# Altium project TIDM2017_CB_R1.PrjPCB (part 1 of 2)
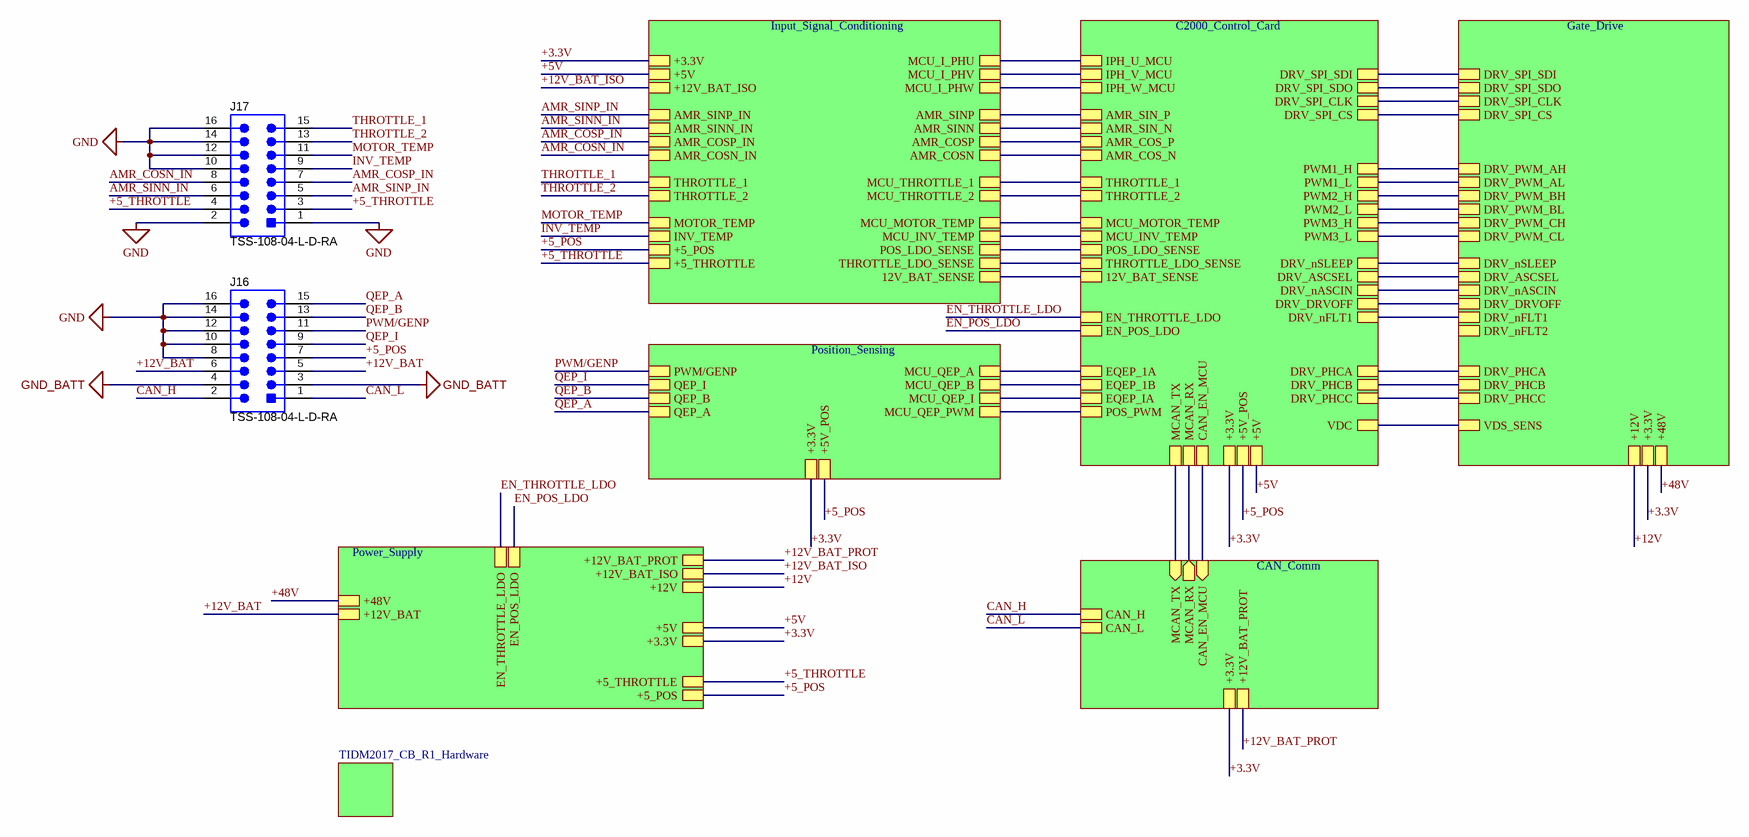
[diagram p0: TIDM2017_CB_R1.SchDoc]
CopyrightYear: 2023; PCB_Layout: Bhanu Vankayalapati; PCB_Rev: C1; PRJ_Customer: Public Release; PRJ_Engineer: Bhanu Vankayalapati; PRJ_Number: TIDM-2017; PRJ_Title: Control_Board_2W_Traction_Inverter; SCH_Rev: C1; TechSupport: http://www.ti.com/support; TID: N/A
8 sheets, 247 parts. Net scope: hierarchical (ports join the sheet entries above them; power ports are global).
Board file: TIDM2017_CB_R1.PcbDoc
Sheets:
  TIDM2017_CB_R1.SchDoc
     = C2000_Control_Card.SchDoc
    Designator = CAN_Comm.SchDoc
    Designator = Input_Signal_Conditioning.SchDoc
    Designator = Gate_Drive.SchDoc
    Designator = Power_Supply.SchDoc
    Designator = Position_Sensing.SchDoc
    Designator = TIDM2017_CB_R1_Hardware.SchDoc

## Sheet TIDM2017_CB_R1.SchDoc
size 431 x 279 mm; Date: Not shown in title block; ApprovedBy: Not shown in title block; CheckedBy: Not shown in title block; Author: Not shown in title block; CompanyName: Not shown in title block; DrawnBy: Bhanu Vankayalapati; Engineer: Not shown in title block; Organization: Not shown in title block; Address1: Not shown in title block; Address2: Not shown in title block; Address3: Not shown in title block; Address4: Not shown in title block; DocumentNumber: 2; Revision: Use project parameter SCH_Rev; SheetNumber: 1; SheetTotal: 2; PageSetup: Record=PageOptions¦CenterHorizontal=True¦CenterVertical=True¦PrintScale=1.00¦XCorrection=1.00¦YCorrection=1.00¦PrintKind=0¦BorderSize=5000000¦LeftOffset=0¦BottomOffset=0¦Orientation=2¦PaperLength=1000¦PaperWidth=1000¦Scale=100¦PaperSource=15¦PrintQuality=600¦MediaType=1¦DitherType=10¦PaperKind=Letter¦PrintScaleMode=1

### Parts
J16  TSS-108-04-L-D-RA  [Samtec_TSS-108-04-x-D-RA]
J17  TSS-108-04-L-D-RA  [Samtec_TSS-108-04-x-D-RA]

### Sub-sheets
Designator = CAN_Comm: MCAN_TX (in), MCAN_RX (out), CAN_H, CAN_L, CAN_EN_MCU (in), +3.3V, +12V_BAT_PROT
Designator = Input_Signal_Conditioning: MCU_I_PHU, MCU_I_PHV, MCU_I_PHW, +3.3V, MCU_THROTTLE_1, MCU_THROTTLE_2, THROTTLE_1, THROTTLE_2, MCU_MOTOR_TEMP, MOTOR_TEMP, AMR_SINP_IN, AMR_SINP, AMR_SINN_IN, AMR_SINN, AMR_COSP_IN, AMR_COSP, AMR_COSN_IN, AMR_COSN, MCU_INV_TEMP, INV_TEMP, +5_POS, POS_LDO_SENSE, +5_THROTTLE, THROTTLE_LDO_SENSE, +5V, +12V_BAT_ISO, 12V_BAT_SENSE
Designator = Gate_Drive: DRV_SPI_SDI, DRV_SPI_SDO, DRV_SPI_CLK, DRV_SPI_CS, DRV_PWM_AH, DRV_PWM_AL, DRV_PWM_BH, DRV_PWM_BL, DRV_PWM_CH, DRV_PWM_CL, DRV_nSLEEP, DRV_ASCSEL, DRV_nASCIN, DRV_DRVOFF, +12V, DRV_PHCA, DRV_PHCB, DRV_PHCC, DRV_nFLT1, DRV_nFLT2, +3.3V, +48V, VDS_SENS
Designator = Power_Supply: +12V, +48V, +12V_BAT_ISO, +5V, EN_THROTTLE_LDO, EN_POS_LDO, +3.3V, +12V_BAT_PROT, +12V_BAT, +5_POS, +5_THROTTLE
Designator = Position_Sensing: MCU_QEP_A, MCU_QEP_B, MCU_QEP_I, PWM/GENP, MCU_QEP_PWM, QEP_A, QEP_B, QEP_I, +3.3V, +5V_POS
Designator = TIDM2017_CB_R1_Hardware: no entries
? = C2000_Control_Card: DRV_SPI_SDI, DRV_SPI_SDO, DRV_SPI_CLK, DRV_SPI_CS, PWM2_H, PWM2_L, PWM1_H, PWM1_L, PWM3_H, PWM3_L, DRV_PHCC, DRV_PHCB, DRV_PHCA, EQEP_IA, EQEP_1A, EQEP_1B, POS_PWM, MCAN_TX, MCAN_RX, CAN_EN_MCU, +3.3V, +5V, +5V_POS, DRV_nFLT1, DRV_DRVOFF, DRV_ASCSEL, DRV_nASCIN, DRV_nSLEEP, IPH_V_MCU, IPH_U_MCU, AMR_COS_P, AMR_SIN_P, THROTTLE_1, AMR_COS_N, AMR_SIN_N, THROTTLE_2, IPH_W_MCU, VDC, THROTTLE_LDO_SENSE, POS_LDO_SENSE, MCU_INV_TEMP, MCU_MOTOR_TEMP, 12V_BAT_SENSE, EN_THROTTLE_LDO, EN_POS_LDO

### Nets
+3.3V: sheet /+3.3V, sheet Designator/+3.3V, sheet Designator/+3.3V, sheet Designator/+3.3V, sheet Designator/+3.3V, sheet Designator/+3.3V
+5V: sheet /+5V, sheet Designator/+5V, sheet Designator/+5V
GND: J16.8 J16.10 J16.12 J16.14 J16.16 J17.1 J17.2 J17.10 J17.12 J17.14 J17.16
GND_BATT: J16.3 J16.4
12V_BAT_SENSE: sheet /12V_BAT_SENSE, sheet Designator/12V_BAT_SENSE
+5_POS: J16.7 ; sheet /+5V_POS, sheet Designator/+5_POS, sheet Designator/+5_POS, sheet Designator/+5V_POS
+5_THROTTLE: J17.3 J17.4 ; sheet Designator/+5_THROTTLE, sheet Designator/+5_THROTTLE
+12V: sheet Designator/+12V, sheet Designator/+12V
+12V_BAT: J16.5 J16.6 ; sheet Designator/+12V_BAT
+12V_BAT_ISO: sheet Designator/+12V_BAT_ISO, sheet Designator/+12V_BAT_ISO  [project net +12_Bat_Iso]
+12V_BAT_PROT: sheet Designator/+12V_BAT_PROT, sheet Designator/+12V_BAT_PROT
+48V: sheet Designator/+48V, sheet Designator/+48V
AMR_COS_N: sheet /AMR_COS_N, sheet Designator/AMR_COSN
AMR_COS_P: sheet /AMR_COS_P, sheet Designator/AMR_COSP
AMR_COSN_IN: J17.8 ; sheet Designator/AMR_COSN_IN
AMR_COSP_IN: J17.7 ; sheet Designator/AMR_COSP_IN
AMR_SIN_N: sheet /AMR_SIN_N, sheet Designator/AMR_SINN
AMR_SIN_P: sheet /AMR_SIN_P, sheet Designator/AMR_SINP
AMR_SINN_IN: J17.6 ; sheet Designator/AMR_SINN_IN
AMR_SINP_IN: J17.5 ; sheet Designator/AMR_SINP_IN
CAN_EN_MCU: sheet /CAN_EN_MCU, sheet Designator/CAN_EN_MCU
CAN_H: J16.2 ; sheet Designator/CAN_H
CAN_L: J16.1 ; sheet Designator/CAN_L
DRV_ASCSEL: sheet /DRV_ASCSEL, sheet Designator/DRV_ASCSEL
DRV_DRVOFF: sheet /DRV_DRVOFF, sheet Designator/DRV_DRVOFF
DRV_nASCIN: sheet /DRV_nASCIN, sheet Designator/DRV_nASCIN
DRV_nFLT1: sheet /DRV_nFLT1, sheet Designator/DRV_nFLT1
DRV_nSLEEP: sheet /DRV_nSLEEP, sheet Designator/DRV_nSLEEP
DRV_PHCA: sheet /DRV_PHCA, sheet Designator/DRV_PHCA
DRV_PHCB: sheet /DRV_PHCB, sheet Designator/DRV_PHCB
DRV_PHCC: sheet /DRV_PHCC, sheet Designator/DRV_PHCC
DRV_PWM_AH: sheet /PWM1_H, sheet Designator/DRV_PWM_AH
DRV_PWM_AL: sheet /PWM1_L, sheet Designator/DRV_PWM_AL
DRV_PWM_BH: sheet /PWM2_H, sheet Designator/DRV_PWM_BH
DRV_PWM_BL: sheet /PWM2_L, sheet Designator/DRV_PWM_BL
DRV_PWM_CH: sheet /PWM3_H, sheet Designator/DRV_PWM_CH
DRV_PWM_CL: sheet /PWM3_L, sheet Designator/DRV_PWM_CL
DRV_SPI_CLK: sheet /DRV_SPI_CLK, sheet Designator/DRV_SPI_CLK
DRV_SPI_CS: sheet /DRV_SPI_CS, sheet Designator/DRV_SPI_CS
DRV_SPI_SDI: sheet /DRV_SPI_SDI, sheet Designator/DRV_SPI_SDI
DRV_SPI_SDO: sheet /DRV_SPI_SDO, sheet Designator/DRV_SPI_SDO
EN_POS_LDO: sheet /EN_POS_LDO, sheet Designator/EN_POS_LDO
EN_THROTTLE_LDO: sheet /EN_THROTTLE_LDO, sheet Designator/EN_THROTTLE_LDO
ILEM_A_MCU: sheet /IPH_U_MCU, sheet Designator/MCU_I_PHU
ILEM_B_MCU: sheet /IPH_V_MCU, sheet Designator/MCU_I_PHV
ILEM_C_MCU: sheet /IPH_W_MCU, sheet Designator/MCU_I_PHW
INV_TEMP: J17.9 ; sheet Designator/INV_TEMP
MCAN_RX: sheet /MCAN_RX, sheet Designator/MCAN_RX
MCAN_TX: sheet /MCAN_TX, sheet Designator/MCAN_TX
MCU_INV_TEMP: sheet /MCU_INV_TEMP, sheet Designator/MCU_INV_TEMP
MCU_MOTOR_TEMP: sheet /MCU_MOTOR_TEMP, sheet Designator/MCU_MOTOR_TEMP
MCU_QEP_A: sheet /EQEP_1A, sheet Designator/MCU_QEP_A
MCU_QEP_B: sheet /EQEP_1B, sheet Designator/MCU_QEP_B
MCU_QEP_I: sheet /EQEP_IA, sheet Designator/MCU_QEP_I
MCU_QEP_PWM: sheet /POS_PWM, sheet Designator/MCU_QEP_PWM
MCU_THROTTLE_1: sheet /THROTTLE_1, sheet Designator/MCU_THROTTLE_1
MCU_THROTTLE_2: sheet /THROTTLE_2, sheet Designator/MCU_THROTTLE_2
MOTOR_TEMP: J17.11 ; sheet Designator/MOTOR_TEMP
POS_LDO_SENSE: sheet /POS_LDO_SENSE, sheet Designator/POS_LDO_SENSE
PWM/GENP: J16.11 ; sheet Designator/PWM/GENP  [project net EQEP_PWM]
QEP_A: J16.15 ; sheet Designator/QEP_A  [project net EQEP_A]
QEP_B: J16.13 ; sheet Designator/QEP_B  [project net EQEP_B]
QEP_I: J16.9 ; sheet Designator/QEP_I  [project net EQEP_I]
THROTTLE_1: J17.15 ; sheet Designator/THROTTLE_1
THROTTLE_2: J17.13 ; sheet Designator/THROTTLE_2
THROTTLE_LDO_SENSE: sheet /THROTTLE_LDO_SENSE, sheet Designator/THROTTLE_LDO_SENSE
VDC: sheet /VDC, sheet Designator/VDS_SENS

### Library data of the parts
J16 J17 = CMP-0075673-1: Header (Shrouded), 2.54mm, 8x2, Tin, R/A, TH; Manufacturer: Samtec; Pitch_mm: 2.54; Gender: Male; Cert_UL: Y; CT: False; Row_Count: 2

## Sheet C2000_Control_Card.SchDoc
size 431 x 279 mm; Date: Not shown in title block; ApprovedBy: Not shown in title block; CheckedBy: Not shown in title block; Author: Not shown in title block; CompanyName: Not shown in title block; Engineer: Not shown in title block; Organization: Not shown in title block; Address1: Not shown in title block; Address2: Not shown in title block; Address3: Not shown in title block; Address4: Not shown in title block; DocumentNumber: 2; Revision: Use project parameter SCH_Rev; SheetNumber: 2; SheetTotal: 3; PageSetup: Record=PageOptions¦CenterHorizontal=True¦CenterVertical=True¦PrintScale=1.00¦XCorrection=1.00¦YCorrection=1.00¦PrintKind=0¦BorderSize=5000000¦LeftOffset=0¦BottomOffset=0¦Orientation=2¦PaperLength=1000¦PaperWidth=1000¦Scale=100¦PaperSource=15¦PrintQuality=600¦MediaType=1¦DitherType=10¦PaperKind=Letter¦PrintScaleMode=1
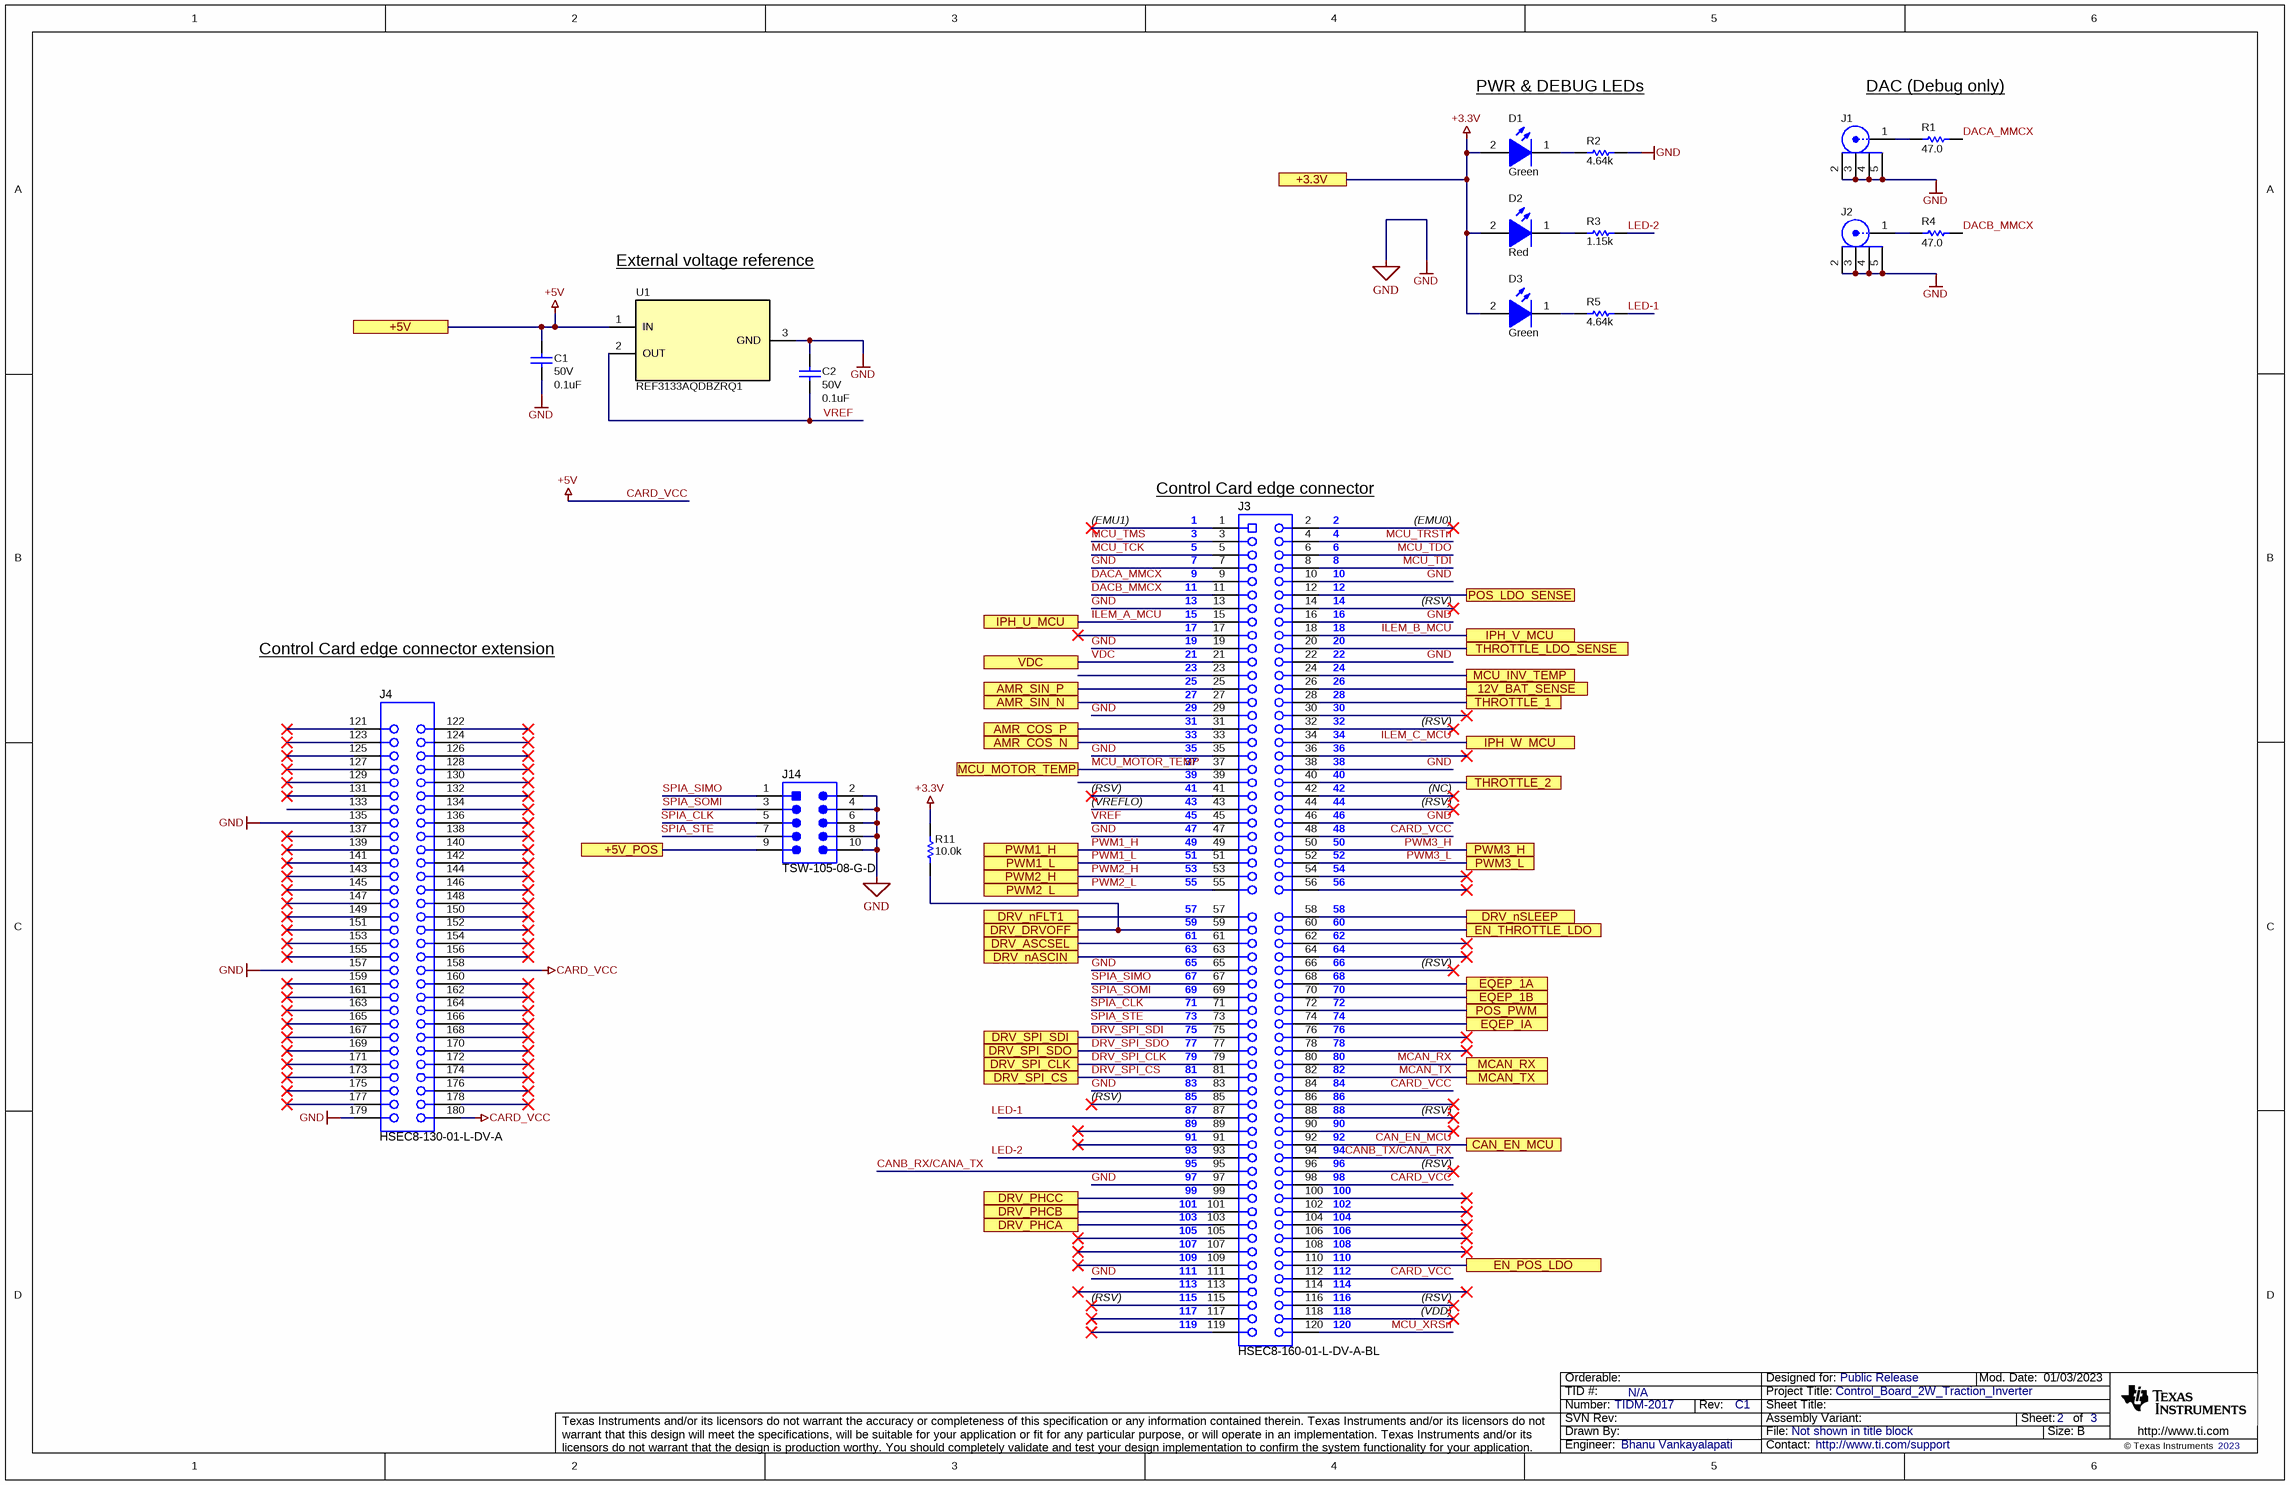
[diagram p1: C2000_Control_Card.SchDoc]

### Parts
C1  VDC_V: 50V  ValueDisplayed: 0.1uF  [0603]  (hidden comment: CGA3E2X7R1H104K080AA)
C2  VDC_V: 50V  ValueDisplayed: 0.1uF  [0603]  (hidden comment: CGA3E2X7R1H104K080AA)
D1  value Green  [WL-SMCW_GREEN]  (hidden comment: 150060GS75000)
D2  value Red  [WL-SMCW_RED]  (hidden comment: 150060RS75000)
D3  value Green  [WL-SMCW_GREEN]  (hidden comment: 150060GS75000)
J1  0734151471  [Molex_0734151471]  (value not drawn)
J2  0734151471  [Molex_0734151471]  (value not drawn)
J3  HSEC8-160-01-L-DV-A-BL  [controlCARD-120HSEC]
J4  HSEC8-130-01-L-DV-A  [controlCARD-180HSEC-60pinAddon]
J14  TSW-105-08-G-D  [Samtec_TSW-105-08-x-D]
R1  ValueDisplayed: 47.0  [0603]  (hidden comment: CRCW060347R0FKEA)
R2  ValueDisplayed: 4.64k  [0603]  (hidden comment: CRCW06034K64FKEA)
R3  ValueDisplayed: 1.15k  [0603]  (hidden comment: CRCW06031K15FKEA)
R4  ValueDisplayed: 47.0  [0603]  (hidden comment: CRCW060347R0FKEA)
R5  ValueDisplayed: 4.64k  [0603]  (hidden comment: CRCW06034K64FKEA)
R11  ValueDisplayed: 10.0k  [0603]  (hidden comment: CRCW060310K0FKEA)
U1  REF3133AQDBZRQ1  [DBZ0003A_N]

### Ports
12V_BAT_SENSE, +3.3V, +5V, +5V_POS, AMR_COS_N, AMR_COS_P, AMR_SIN_N, AMR_SIN_P, CAN_EN_MCU, DRV_ASCSEL, DRV_DRVOFF, DRV_nASCIN, DRV_nFLT1, DRV_nSLEEP, DRV_PHCA, DRV_PHCB, DRV_PHCC, DRV_SPI_CLK, DRV_SPI_CS, DRV_SPI_SDI, DRV_SPI_SDO, EN_POS_LDO, EN_THROTTLE_LDO, EQEP_1A, EQEP_1B, EQEP_IA, IPH_U_MCU, IPH_V_MCU, IPH_W_MCU, MCAN_RX, MCAN_TX, MCU_INV_TEMP, MCU_MOTOR_TEMP, POS_LDO_SENSE, POS_PWM, PWM1_H, PWM1_L, PWM2_H, PWM2_L, PWM3_H, PWM3_L, THROTTLE_1, THROTTLE_2, THROTTLE_LDO_SENSE, VDC

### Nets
+3.3V: D1.2(A) D2.2(A) D3.2(A) R11.2 ; port +3.3V
+5V: C1.1 J3.48 J3.84 J3.98 J3.112 J4.158 J4.180 U1.1(IN) ; port +5V  [also labelled CARD_VCC]
GND: C1.2 C2.1 J1.2 J1.3 J1.4 J1.5 J2.2 J2.3 J2.4 J2.5 J3.7 J3.10 J3.13 J3.16 J3.19 J3.22 J3.29 J3.35 J3.38 J3.46 J3.47 J3.65 J3.83 J3.97 J3.111 J4.135 J4.157 J4.179 J14.2 J14.4 J14.6 J14.8 J14.10 R2.1 U1.3(GND)
12V_BAT_SENSE: J3.26 ; port 12V_BAT_SENSE
+5_POS: J14.9 ; port +5V_POS
AMR_COS_N: J3.33 ; port AMR_COS_N
AMR_COS_P: J3.31 ; port AMR_COS_P
AMR_SIN_N: J3.27 ; port AMR_SIN_N
AMR_SIN_P: J3.25 ; port AMR_SIN_P
CAN_EN_MCU: J3.92 ; port CAN_EN_MCU
CANB_RX/CANA_TX: J3.95
CANB_TX/CANA_RX: J3.94
DACA_MMCX: J3.9 R1.2
DACB_MMCX: J3.11 R4.2
DRV_ASCSEL: J3.61 ; port DRV_ASCSEL
DRV_DRVOFF: J3.59 R11.1 ; port DRV_DRVOFF
DRV_nASCIN: J3.63 ; port DRV_nASCIN
DRV_nFLT1: J3.57 ; port DRV_nFLT1
DRV_nSLEEP: J3.58 ; port DRV_nSLEEP
DRV_PHCA: J3.103 ; port DRV_PHCA
DRV_PHCB: J3.101 ; port DRV_PHCB
DRV_PHCC: J3.99 ; port DRV_PHCC
DRV_SPI_CLK: J3.79 ; port DRV_SPI_CLK
DRV_SPI_CS: J3.81 ; port DRV_SPI_CS
DRV_SPI_SDI: J3.75 ; port DRV_SPI_SDI
DRV_SPI_SDO: J3.77 ; port DRV_SPI_SDO
EN_POS_LDO: J3.110 ; port EN_POS_LDO
EN_THROTTLE_LDO: J3.60 ; port EN_THROTTLE_LDO
ILEM_A_MCU: J3.15 ; port IPH_U_MCU
ILEM_B_MCU: J3.18 ; port IPH_V_MCU
ILEM_C_MCU: J3.34 ; port IPH_W_MCU
LED-1: J3.87 R5.1
LED-2: J3.93 R3.1
MCAN_RX: J3.80 ; port MCAN_RX
MCAN_TX: J3.82 ; port MCAN_TX
MCU_INV_TEMP: J3.24 ; port MCU_INV_TEMP
MCU_MOTOR_TEMP: J3.37 ; port MCU_MOTOR_TEMP
MCU_QEP_A: J3.68 ; port EQEP_1A
MCU_QEP_B: J3.70 ; port EQEP_1B
MCU_QEP_I: J3.74 ; port EQEP_IA
MCU_QEP_PWM: J3.72 ; port POS_PWM
MCU_TCK: J3.5
MCU_TDI: J3.8
MCU_TDO: J3.6
MCU_THROTTLE_1: J3.28 ; port THROTTLE_1
MCU_THROTTLE_2: J3.40 ; port THROTTLE_2
MCU_TMS: J3.3
MCU_TRSTn: J3.4
MCU_XRSn: J3.120
POS_LDO_SENSE: J3.12 ; port POS_LDO_SENSE
PWM1_H: J3.49 ; port PWM1_H  [project net DRV_PWM_AH]
PWM1_L: J3.51 ; port PWM1_L  [project net DRV_PWM_AL]
PWM2_H: J3.53 ; port PWM2_H  [project net DRV_PWM_BH]
PWM2_L: J3.55 ; port PWM2_L  [project net DRV_PWM_BL]
PWM3_H: J3.50 ; port PWM3_H  [project net DRV_PWM_CH]
PWM3_L: J3.52 ; port PWM3_L  [project net DRV_PWM_CL]
SPIA_CLK: J3.71 J14.5
SPIA_SIMO: J3.67 J14.1
SPIA_SOMI: J3.69 J14.3
SPIA_STE: J3.73 J14.7
THROTTLE_LDO_SENSE: J3.20 ; port THROTTLE_LDO_SENSE
VDC: J3.21 ; port VDC
VREF: C2.2 J3.45 U1.2(OUT)
NetD1_1: D1.1(K) R2.2
NetD2_1: D2.1(K) R3.2
NetD3_1: D3.1(K) R5.2
NetJ1_1: J1.1 R1.1
NetJ2_1: J2.1 R4.1

Not connected (* = marked no-connect by the designer): J3 1* 2* 14* 17* 23 30* 32* 36* 39 41* 42* 43 44* 54* 56* 62* 64* 66* 76* 78* 85* 86* 88* 89* 90* 91* 96* 100* 102* 104* 105* 106* 107* 108* 109* 113* 114* 115* 116* 117* 118* 119*; J4 121* 122* 123* 124* 125* 126* 127* 128* 129* 130* 131* 132* 133 134* 136* 137* 138* 139* 140* 141* 142* 143* 144* 145* 146* 147* 148* 149* 150* 151* 152* 153* 154* 155* 156* 159* 160* 161* 162* 163* 164* 165* 166* 167* 168* 169* 170* 171* 172* 173* 174* 175* 176* 177* 178*

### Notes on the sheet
- PWR & DEBUG LEDs
- DAC (Debug only)
- External voltage reference
- (near J3) Control Card edge connector
- (EMU1)
- (near J3) 1
- (near J3) 3
- (near J3) 5
- (near J3) 7
- (near J3) 2
- (near J3) 4
- (near J3) 6
- (near J3) 8
- (EMU0)
- (near J3) 9
- (near J3) 11
- (near J3) 13
- (near J3) 15
- (near J3) 17
- (near J3) 10
- (near J3) 12
- (near J3) 14
- (near J3) 16
- (near J3) 18
- (RSV)
- Control Card edge connector extension
- (near J3) 19
- (near J3) 21
- (near J3) 23
- (near J3) 25
- (near J3) 27
- (near J3) 22
- (near J3) 20
- (near J3) 24
- (near J3) 26
- (near J3) 28
- (near J3) 29
- (near J3) 31
- (near J3) 33
- (near J3) 35
- (near J3) 37
- (near J3) 30
- (near J3) 32
- (near J3) 34
- (near J3) 36
- (near J3) 38
- (VREFLO)
- (near J3) 39
- (near J3) 41
- (near J3) 43
- (near J3) 45
- (near J3) 47
- (near J3) 40
- (near J3) 42
- (near J3) 44
- (near J3) 46
- (near J3) 48
- (NC)
- (near J3) 49
- (near J3) 51
- (near J3) 53
- (near J3) 55
- (near J3) 50
- (near J3) 52
- (near J3) 54
- (near J3) 56
- (near J3) 61
- (near J3) 65
- (near J3) 59
- (near J3) 57
- (near J3) 63
- (near J3) 58
- (near J3) 60
- (near J3) 66
- (near J3) 62
- (near J3) 64
- (near J3) 67
- (near J3) 69
- (near J3) 71
- (near J3) 73
- (near J3) 75
- (near J3) 68
- (near J3) 70
- (near J3) 72
- (near J3) 74
- (near J3) 76
- (near J3) 77
- (near J3) 79
- (near J3) 81
- (near J3) 83
- (near J3) 85
- (near J3) 78
- (near J3) 80
- (near J3) 82
- (near J3) 84
- (near J3) 86
- (near J3) 87
- (near J3) 89
- (near J3) 91
- (near J3) 93
- (near J3) 95
- (near J3) 88
- (near J3) 90
- (near J3) 92
- (near J3) 94
- (near J3) 96
- (near J3) 97
- (near J3) 99
- (near J3) 101
- (near J3) 103
- (near J3) 105
- (near J3) 98
- (near J3) 100
- (near J3) 102
- (near J3) 104
- (near J3) 106
- (near J3) 107
- (near J3) 109
- (near J3) 111
- (near J3) 113
- (near J3) 115
- (near J3) 108
- (near J3) 110
- (near J3) 112
- (near J3) 114
- (near J3) 116
- (near J3) 117
- (near J3) 119
- (near J3) 118
- (near J3) 120
- (VDD)

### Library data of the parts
C1 C2 = CMP-0007078-4: CAP, CERM, 0.1 uF, 50 V, +/- 10%, X7R, AEC-Q200 Grade 1, 0603; Manufacturer: TDK; TaMin_C: -55°C; ESR_ohm: 29.6m; Polarized: N; SizeAreaWB_mm2: 4.68; Value1: 0.0296 ohm; U/M: EA; Value: 0.1uF; TaMax_C: 125°C; SizeZ_mm: 1; SizeX_mm: 1.6; SizeY_mm: 0.8; SizeArea_mm2: 1.28; AEC Qualified: Y; Cap_F: 100nF; IRMS_A: 971.99mA; AEC Category: Q200
D1 D3 = CMP-0002905-2: LED, Green, SMD; Manufacturer: Wurth Elektronik; Type: InGaN; Vf_V: 3.2V; Io_A: 20mA; Tjmax_C: 85°C; Value1: W; Angle: 140
D2 = CMP-0002947-3: LED, Red, SMD; Manufacturer: Wurth Elektronik; Value1: 0.072W; Vf_V: 2V; Angle: 140; Tjmax_C: 85°C; Type: AlInGaP; Vr_V: 5V; Io_A: 30mA; Power_TotalModule: 72mW
J1 J2 = CMP-0055255-2: MMCX JACK, 50 Ohm, Gold, TH; Manufacturer: Molex; CT: FALSE; Gender: Female
J3 = CMP-0003814-2: C2000 controlCARD-120HSEC connector, SMT; Manufacturer: Samtec; Note: The pin numbering does not match Samtec datasheet
J4 = CMP-0003859-2: C2000 controlCARD-180HSEC (60-pin addon) connector, SMT; Manufacturer: Samtec; Note: The pin numbering does not match Samtec datasheet
J14 = CMP-0860034-1: Header, 2.54mm, 5x2, Gold, TH; Manufacturer: Samtec; Pitch_mm: 2.54; Shrouded: N; Row_Count: 2; Cert_UL: Y; Gender: Male
R1 R4 = CMP-0081280-1: RES, 47.0, 1%, 0.1 W, AEC-Q200 Grade 0, 0603; Manufacturer: Vishay-Dale; Value: 47.0; Res_ohm: 47; Value_Code: 47R0; Power_W: 100mW; Value2: 0.1W; VDC_V: 75V; TempCo: 100 ppm/C; SizeArea_mm2: 1.28; SizeX_mm: 1.6; SizeY_mm: 0.8; SizeZ_mm: 1; AEC Category: Q200; AEC Qualified: Y; AEC Grade: 0; SizeAreaWB_mm2: 4.68
R2 R5 = CMP-0022455-4: RES, 4.64 k, 1%, 0.1 W, AEC-Q200 Grade 0, 0603; Manufacturer: Vishay-Dale; Power_W: 100mW; TempCo: 100 ppm/C; Value_Code: 4k64; Value: 4.64k; SizeX_mm: 1.6; SizeY_mm: 0.8; SizeZ_mm: 1; Value2: 0.1W; SizeArea_mm2: 1.28; AEC Qualified: Y; VDC_V: 75V; AEC Category: Q200; AEC Grade: 0; EIA_Code: E96
R3 = CMP-0022115-4: RES, 1.15 k, 1%, 0.1 W, AEC-Q200 Grade 0, 0603; Manufacturer: Vishay-Dale; Power_W: 100mW; TempCo: 100 ppm/C; Value_Code: 1k15; Value: 1.15k; SizeX_mm: 1.6; SizeY_mm: 0.8; SizeZ_mm: 1; Value2: 0.1W; SizeArea_mm2: 1.28; AEC Qualified: Y; VDC_V: 75V; AEC Category: Q200; AEC Grade: 0; EIA_Code: E96
R11 = CMP-0021998-4: RES, 10.0 k, 1%, 0.1 W, AEC-Q200 Grade 0, 0603; Manufacturer: Vishay-Dale; Power_W: 100mW; TempCo: 100 ppm/C; Value_Code: 10k0; Value: 10.0k; EIA_Code: E96; Res_ohm: 10k; SizeX_mm: 1.6; SizeY_mm: 0.8; SizeZ_mm: 1; Value2: 0.1W; SizeArea_mm2: 1.28; AEC Qualified: Y; VDC_V: 75V; AEC Category: Q200; AEC Grade: 0
U1 = CMP-0079649-1: Automotive 20 ppm / degC Max, 100 uA, SOT23-3 Series Voltage Reference, DBZ0003A (SOT-23-3); Alternate PartNumber: REF3133AQDBZTQ1; Alternate Manufacturer: Texas Instruments; SizeAreaWB_mm2: 14; SizeZ_mm: 1.12; SizeX_mm: 2.5; SizeY_mm: 3; SizeArea_mm2: 7.5; CompType: IC; AEC Qualified: Y; AEC Category: Q200

## Sheet CAN_Comm.SchDoc
size 431 x 279 mm; Date: Not shown in title block; ApprovedBy: Not shown in title block; CheckedBy: Not shown in title block; Author: Not shown in title block; CompanyName: Not shown in title block; Engineer: Not shown in title block; Organization: Not shown in title block; Address1: Not shown in title block; Address2: Not shown in title block; Address3: Not shown in title block; Address4: Not shown in title block; DocumentNumber: 2; Revision: Use project parameter SCH_Rev; SheetNumber: 2; SheetTotal: 3; PageSetup: Record=PageOptions¦CenterHorizontal=True¦CenterVertical=True¦PrintScale=1.00¦XCorrection=1.00¦YCorrection=1.00¦PrintKind=0¦BorderSize=5000000¦LeftOffset=0¦BottomOffset=0¦Orientation=2¦PaperLength=1000¦PaperWidth=1000¦Scale=100¦PaperSource=15¦PrintQuality=600¦MediaType=1¦DitherType=10¦PaperKind=Letter¦PrintScaleMode=1
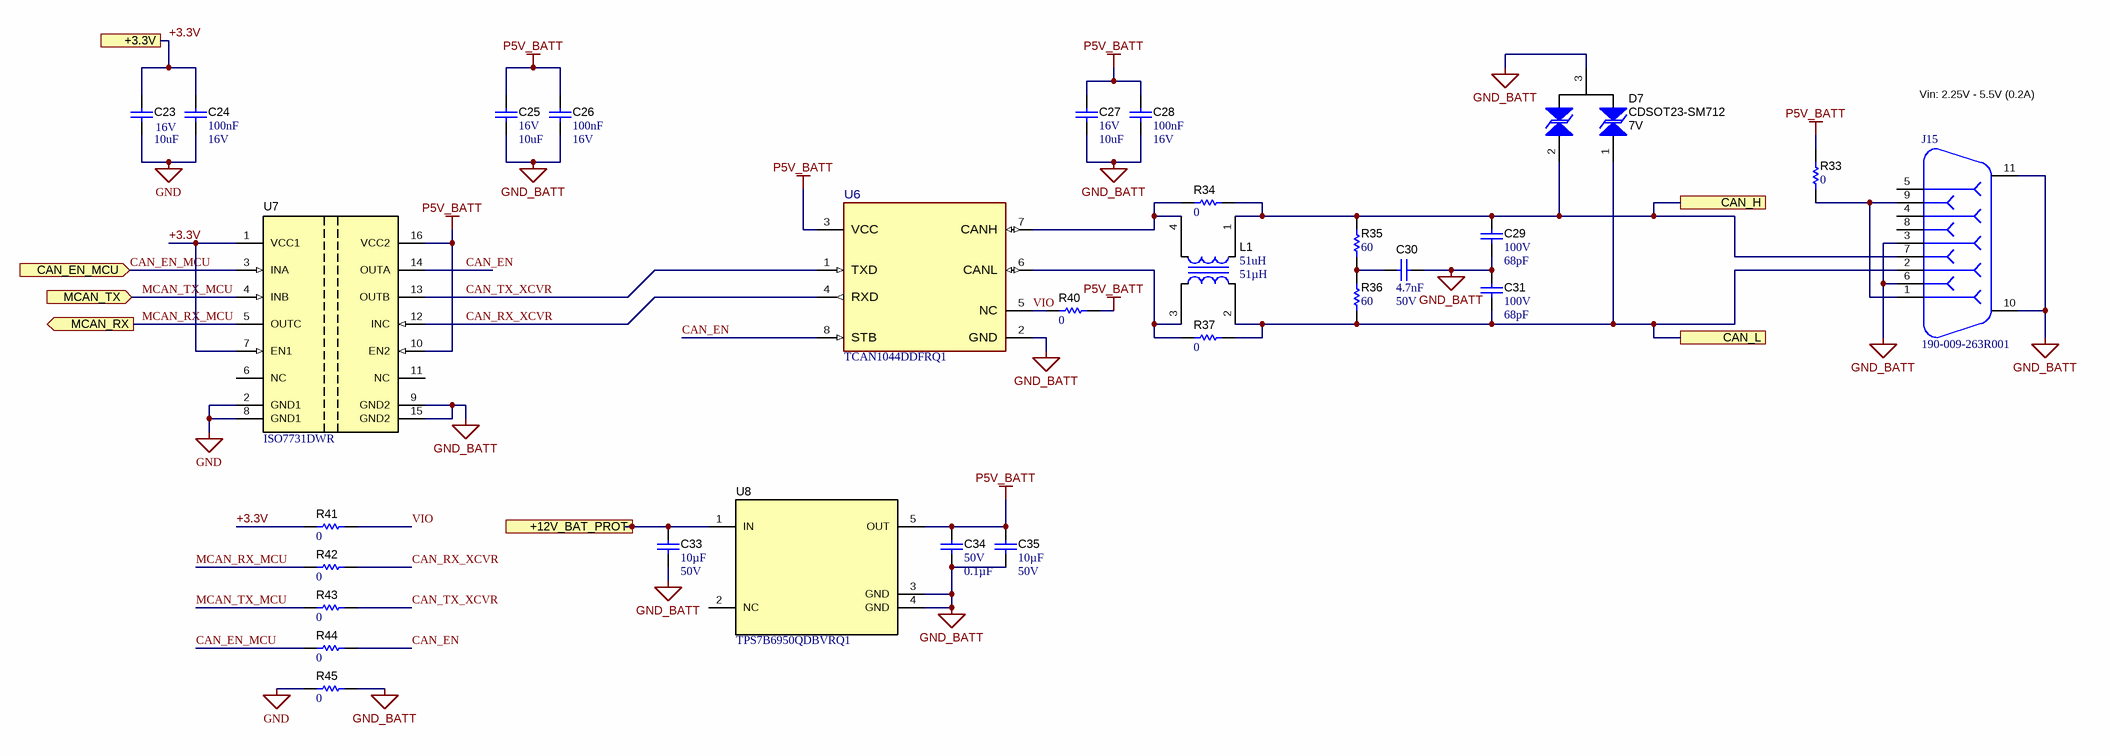
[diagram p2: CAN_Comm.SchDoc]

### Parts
C23  VDC_V: 16V  ValueDisplayed: 10uF  [0805_HV]  (hidden comment: CGA4J1X7S1C106K125AC)
C24  Cap_F: 100nF  VDC_V: 16V  [0603]  (hidden comment: 0603YC104K4T4A)
C25  VDC_V: 16V  ValueDisplayed: 10uF  [0805_HV]  (hidden comment: CGA4J1X7S1C106K125AC)
C26  Cap_F: 100nF  VDC_V: 16V  [0603]  (hidden comment: 0603YC104K4T4A)
C27  VDC_V: 16V  ValueDisplayed: 10uF  [0805_HV]  (hidden comment: CGA4J1X7S1C106K125AC)
C28  Cap_F: 100nF  VDC_V: 16V  [0603]  (hidden comment: 0603YC104K4T4A)
C29  VDC_V: 100V  ValueDisplayed: 68pF  [0603]  (hidden comment: GRM1885C2A680JA01D)
C30  Cap_F: 4.7nF  VDC_V: 50V  [0603]  (hidden comment: GCM188R71H472KA37D)
C31  VDC_V: 100V  ValueDisplayed: 68pF  [0603]  (hidden comment: GRM1885C2A680JA01D)
C33  ValueDisplayed: 10µF  VDC_V: 50V  [1206_190]  (hidden comment: CGA5L1X7R1H106K160AC)
C34  VDC_V: 50V  ValueDisplayed: 0.1µF  [0603]  (hidden comment: CGA3E3X8R1H104K080AE)
C35  ValueDisplayed: 10µF  VDC_V: 50V  [1206_190]  (hidden comment: CGA5L1X7R1H106K160AC)
D7  CDSOT23-SM712  value 7V  [SOT-23]
J15  190-009-263R001  [NORCOMP_190-009-263R001]
L1  value 51uH  ValueDisplayed: 51µH  [ACT45B_NoSilk]  (hidden comment: ACT45B-510-2P-TL003)
R33  ValueDisplayed: 0  [0603]  (hidden comment: RMCF0603ZT0R00)
R34  ValueDisplayed: 0  [0603]  (hidden comment: PMR03EZPJ000)
R35  ValueDisplayed: 60  [1206]  (hidden comment: CRCW120660R0KNEAIF)
R36  ValueDisplayed: 60  [1206]  (hidden comment: CRCW120660R0KNEAIF)
R37  ValueDisplayed: 0  [0603]  (hidden comment: PMR03EZPJ000)
R40  ValueDisplayed: 0  [0603]  (hidden comment: PMR03EZPJ000)
R41  ValueDisplayed: 0  [0805_HV]  (hidden comment: CRCW08050000Z0EAHP)
R42  ValueDisplayed: 0  [0805_HV]  (hidden comment: CRCW08050000Z0EAHP)
R43  ValueDisplayed: 0  [0805_HV]  (hidden comment: CRCW08050000Z0EAHP)
R44  ValueDisplayed: 0  [0805_HV]  (hidden comment: CRCW08050000Z0EAHP)
R45  ValueDisplayed: 0  [0805_HV]  (hidden comment: CRCW08050000Z0EAHP)
U6  TCAN1044DDFRQ1  [DDF0008A-MFG]
U7  ISO7731DWR  [DW0016B_HV]
U8  TPS7B6950QDBVRQ1  [DBV0005A_N]

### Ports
+3.3V, +12V_BAT_PROT, CAN_EN_MCU (in), CAN_H, CAN_L, MCAN_RX (out), MCAN_TX (in)

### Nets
+3.3V: C23.1 C24.1 R41.1 U7.1(VCC1) U7.7(EN1) ; port +3.3V
GND: C23.2 C24.2 R45.1 U7.2(GND1) U7.8(GND1)
GND_BATT: C25.2 C26.2 C27.2 C28.2 C29.2 C30.1 C31.1 C33.2 C34.2 C35.2 D7.3 J15.3 J15.6 J15.10 J15.11 R45.2 U6.2(GND) U7.9(GND2) U7.15(GND2) U8.3(GND) U8.4(GND)
P5V_BATT: C25.1 C26.1 C27.1 C28.1 C34.1 C35.1 R33.2 R40.2 U6.3(VCC) U7.10(EN2) U7.16(VCC2) U8.5(OUT)
+12V_BAT_PROT: C33.1 U8.1(IN) ; port +12V_BAT_PROT
CAN_EN: R44.2 U6.8(STB) U7.14(OUTA)
CAN_EN_MCU: R44.1 U7.3(INA) ; port CAN_EN_MCU
CAN_H: C29.1 D7.2 J15.7 L1.1 R34.2 R35.2 ; port CAN_H
CAN_L: C31.2 D7.1 J15.2 L1.2 R36.1 R37.2 ; port CAN_L
CAN_RX_XCVR: R42.2 U6.4(RXD) U7.12(INC)
CAN_TX_XCVR: R43.2 U6.1(TXD) U7.13(OUTB)
MCAN_RX_MCU: R42.1 U7.5(OUTC) ; port MCAN_RX  [project net MCAN_RX]
MCAN_TX_MCU: R43.1 U7.4(INB) ; port MCAN_TX  [project net MCAN_TX]
VIO: R40.1 R41.2 U6.5(NC)
NetC30_2: C30.2 R35.1 R36.2
NetJ15_1: J15.1 J15.9 R33.1
NetL1_3: L1.3 R37.1 U6.6(CANL)
NetL1_4: L1.4 R34.1 U6.7(CANH)

Not connected (* = marked no-connect by the designer): J15 4 5 8; U7 6(NC) 11(NC); U8 2(NC)

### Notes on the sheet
- Vin: 2.25V - 5.5V (0.2A)

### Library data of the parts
C23 C25 C27 = CMP-0007965-2: CAP, CERM, 10 uF, 16 V, +/- 10%, X7S, AEC-Q200 Grade 1, 0805; Manufacturer: TDK; TaMin_C: -55°C; Polarized: N; SizeAreaWB_mm2: 6.75; Value1: Unknown; U/M: EA; Value: 10uF; TaMax_C: 125°C; SizeZ_mm: 1.45; SizeX_mm: 2; SizeY_mm: 1.25; Cap_Case: 0805; SizeArea_mm2: 2.5; AEC Qualified: Y; Cap_F: 10µF; AEC Grade: 1; AEC Category: Q200
C24 C26 C28 = CMP-0083626-1: CAP, CERM, 0.1 µF, 16 V,+/- 10%, X7R, AEC-Q200 Grade 1, 0603; Manufacturer: AVX; SizeAreaWB_mm2: 4.68; SizeArea_mm2: 1.28; AEC Qualified: Y; AEC Category: Q200; Value: 0.1uF; TaMax_C: 125°C; SizeZ_mm: 1; Polarized: N; TaMin_C: -55°C; SizeY_mm: 0.8; U/M: EA; SizeX_mm: 1.6; ValueDisplayed: 0.1µF
C29 C31 = CMP-0007280-4: CAP, CERM, 68 pF, 100 V, +/- 5%, C0G/NP0, 0603; Manufacturer: MuRata; TaMin_C: -55°C; Polarized: N; SizeAreaWB_mm2: 4.68; Value1: Unknown; U/M: EA; Value: 68pF; TaMax_C: 125°C; SizeZ_mm: 1; SizeX_mm: 1.6; SizeY_mm: 0.8; SizeArea_mm2: 1.28; AEC Category: Q200
C30 = CMP-0007146-4: CAP, CERM, 4700 pF, 50 V, +/- 10%, X7R, AEC-Q200 Grade 1, 0603; Manufacturer: MuRata; TaMin_C: -55°C; Polarized: N; SizeAreaWB_mm2: 4.68; Value1: Unknown; U/M: EA; Value: 4700pF; TaMax_C: 125°C; SizeZ_mm: 1; SizeX_mm: 1.6; SizeY_mm: 0.8; SizeArea_mm2: 1.28; AEC Qualified: Y; AEC Category: Q200
C33 C35 = CMP-0085950-1: CAP, CERM, 10 µF, 50 V,+/- 10%, X7R, AEC-Q200 Grade 1, 1206; Manufacturer: TDK; SizeZ_mm: 1.9; Value: 10uF; Cap_Case: 1206; AEC Grade: 1; TaMin_C: -55°C; U/M: EA; SizeArea_mm2: 5.12; TaMax_C: 125°C; AEC Qualified: Y; AEC Category: Q200; SizeX_mm: 3.2; SizeY_mm: 1.6; Polarized: N; SizeAreaWB_mm2: 10.92
C34 = CMP-0079911-1: CAP, CERM, 0.1 µF, 50 V,+/- 10%, X8R, AEC-Q200 Grade 0, 0603; Manufacturer: TDK; Cap_F: 100nF; SizeAreaWB_mm2: 4.68; SizeArea_mm2: 1.28; AEC Qualified: Y; AEC Category: Q200; Value: 0.1uF; TaMax_C: 150°C; SizeZ_mm: 1; AEC Grade: 0; Polarized: N; TaMin_C: -55°C; SizeY_mm: 0.8; U/M: EA; SizeX_mm: 1.6
D7 = CMP-0005928-2: Diode, TVS, Bi, 7 V, SOT-23; Manufacturer: Bourns; AEC Category: Q101; SizeX_mm: 2.5; SizeY_mm: 3; Ppk: 400W; SizeAreaWB_mm2: 14; SizeZ_mm: 1.1; SizeArea_mm2: 7.5
J15 = CMP-0074875-1: Receptacle, D-Sub, 9 Position, R/A, SMT; Manufacturer: NorComp; CNHeader: False; Green_Lifecycle: Not Set; Gender: Female; Green_REACh: Incomplete; Row_Count: 2; ContactFinish: Gold; CT: True
L1 = CMP-0076845-1: Coupled inductor, 51 µH, 0.2 A, 1 ohm, AEC-Q200 Grade 0, SMD; Manufacturer: TDK; SizeAreaWB_mm2: 23.1; SizeArea_mm2: 14.4; AEC Qualified: Y; AEC Category: Q200; SizeZ_mm: 3.0; Green_REACh: Passed; AEC Grade: 0; SizeY_mm: 3.2; Green_Lifecycle: Active; DCR_ohm: 1; SizeX_mm: 4.5
R33 = CMP-0023343-3: RES, 0, 1%, 0.1 W, AEC-Q200 Grade 0, 0603; Manufacturer: Stackpole Electronics Inc; Power_W: 100mW; TempCo: ppm/C; U/M: EA; Value: 0; SizeX_mm: 1.6; SizeY_mm: 0.8; SizeZ_mm: 1; Value2: 0.1W; SizeArea_mm2: 1.28; AEC Qualified: Y; AEC Category: Q200
R34 R37 R40 = CMP-0086358-1: RES, 0, 0%, 0.25 W, AEC-Q200 Grade 0, 0603; Manufacturer: Rohm; Power_W: 250mW; SizeZ_mm: 1; SizeArea_mm2: 1.28; Value2: 0.25W; SizeAreaWB_mm2: 4.68; Value_Code: 0000; Value: 0; AEC Qualified: Y; AEC Category: Q200; SizeX_mm: 1.6; SizeY_mm: 0.8
R35 R36 = CMP-0018709-3: RES, 60, 10%, 0.25 W, AEC-Q200 Grade 0, 1206; Manufacturer: Vishay-Dale; Power_W: 250mW; TempCo: 200 ppm/C; Value_Code: 60R0; Value: 60; SizeX_mm: 3.2; SizeY_mm: 1.6; SizeZ_mm: 1.35; Value2: 0.25W; SizeArea_mm2: 5.12; AEC Qualified: Y; AEC Grade: 0; AEC Category: Q200
R41-R45 = CMP-0020443-3: RES, 0, 5%, 0.333 W, AEC-Q200 Grade 0, 0805; Manufacturer: Vishay-Dale; Power_W: 333mW; TempCo: 200 ppm/C; Value_Code: 0000; Value: 0; EIA_Code: E24; SizeX_mm: 2; SizeY_mm: 1.25; SizeZ_mm: 1.45; Value2: 0.333W; SizeArea_mm2: 2.5; AEC Qualified: Y; AEC Category: Q200; VDC_V: 150V
U6 = CMP-0089901-1: Automotive High Speed CAN Transceiver; Manufacturer: Texas Instruments; Min Supply Voltage: 4.5V; TaMin_C: -40°C; AEC Grade: Grade 1; Standoff Height: 0mm; SizeZ_mm: 1.1mm; TaMax_C: +125°C; Max Supply Voltage: 5.5V; Nominal Supply Current: 5-180mA; TJmax_C: +150°C; AEC Qualified: Yes
U7 = CMP-0078446-2: High Speed, Robust EMC Triple-Channel Digital Isolators, DW0016B (SOIC-16); Manufacturer: Texas Instruments; AEC Qualified: N; CompType: IC; Rating: Catalog; SizeArea_mm2: 107.12; SizeX_mm: 10.4; SizeAreaWB_mm2: 152.52; AEC Category: Q200; SizeZ_mm: 2.65; SizeY_mm: 10.3
U8 = CMP-0077329-2: Automotive High-Voltage Ultra-Low IQ Low-Dropout Regulator/Fixed 5-V Output Voltage, DBV0005A (SOT-23-5); Manufacturer: Texas Instruments; SizeArea_mm2: 8.12; CompType: IC; SizeAreaWB_mm2: 14.82; SizeY_mm: 2.9; SizeZ_mm: 1.45; SizeX_mm: 2.8; AEC Category: Q200; AEC Qualified: Y

## Sheet Input_Signal_Conditioning.SchDoc
size 431 x 279 mm; Date: Not shown in title block; ApprovedBy: Not shown in title block; CheckedBy: Not shown in title block; Author: Not shown in title block; CompanyName: Not shown in title block; Engineer: Not shown in title block; Organization: Not shown in title block; Address1: Not shown in title block; Address2: Not shown in title block; Address3: Not shown in title block; Address4: Not shown in title block; DocumentNumber: 2; Revision: Use project parameter SCH_Rev; SheetNumber: 2; SheetTotal: 3; PageSetup: Record=PageOptions¦CenterHorizontal=True¦CenterVertical=True¦PrintScale=1.00¦XCorrection=1.00¦YCorrection=1.00¦PrintKind=0¦BorderSize=5000000¦LeftOffset=0¦BottomOffset=0¦Orientation=2¦PaperLength=1000¦PaperWidth=1000¦Scale=100¦PaperSource=15¦PrintQuality=600¦MediaType=1¦DitherType=10¦PaperKind=Letter¦PrintScaleMode=1
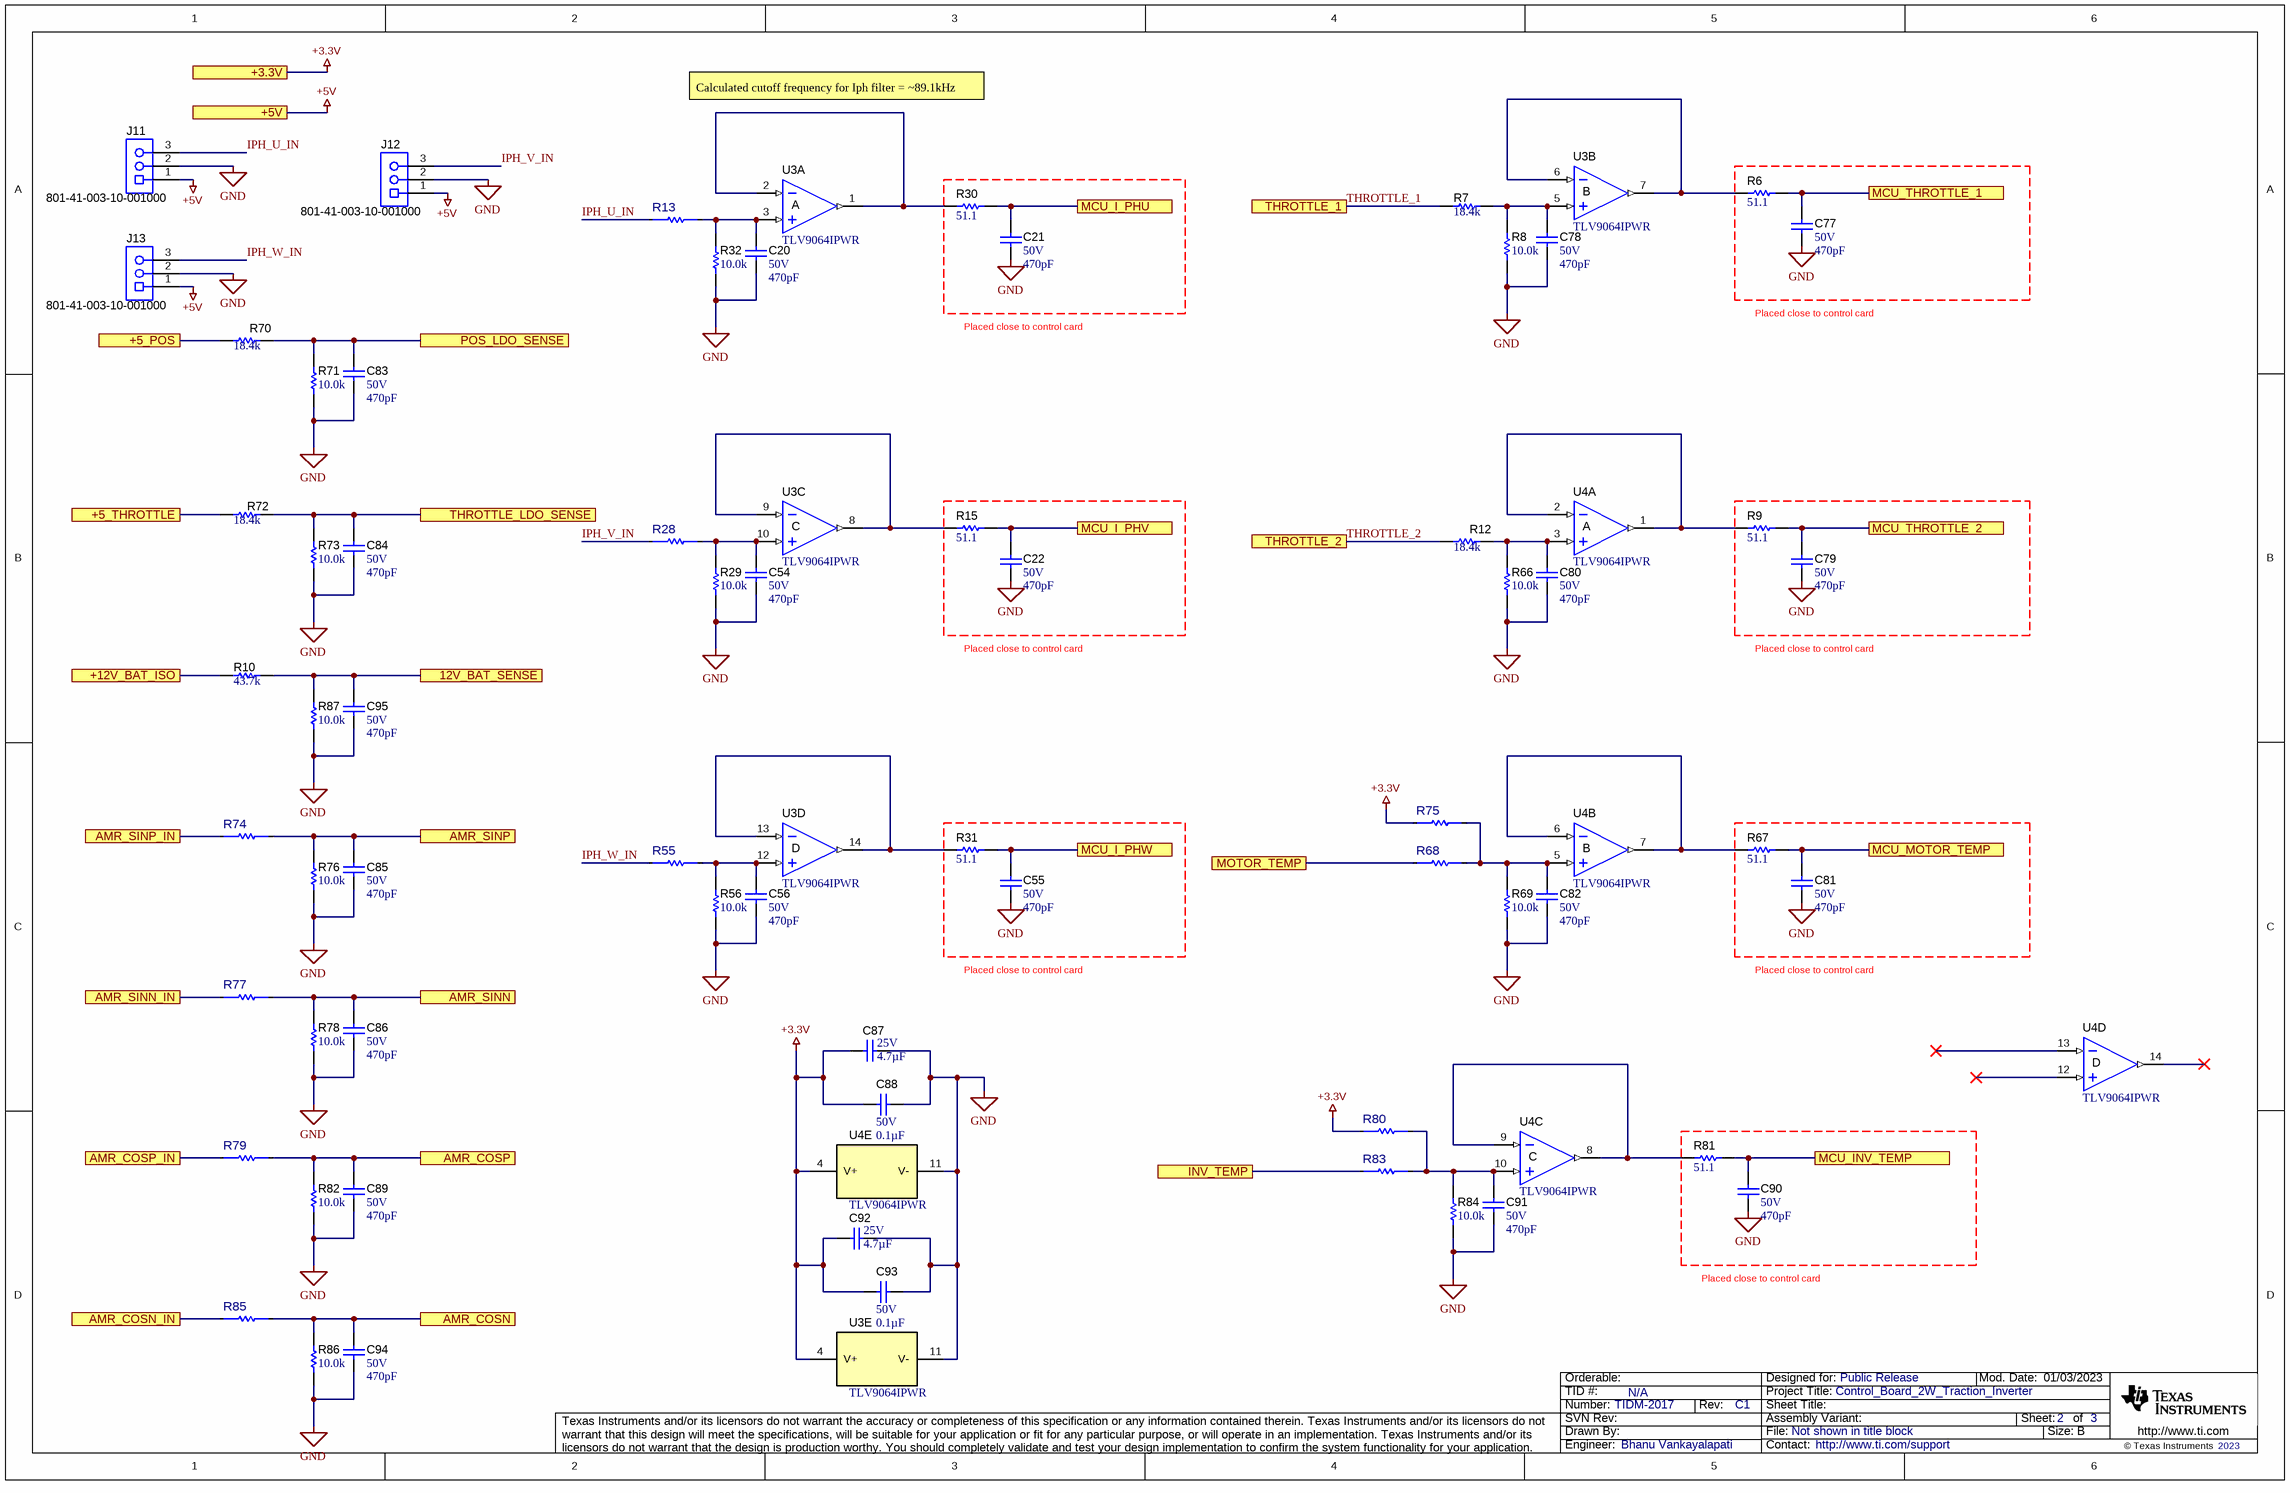
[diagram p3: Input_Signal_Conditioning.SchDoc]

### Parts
C20  VDC_V: 50V  ValueDisplayed: 470pF  [0603]  (hidden comment: GCM1885C1H471JA16D)
C21  VDC_V: 50V  ValueDisplayed: 470pF  [0603]  (hidden comment: GRM1885C1H471JA01D)
C22  VDC_V: 50V  ValueDisplayed: 470pF  [0603]  (hidden comment: GRM1885C1H471JA01D)
C54  VDC_V: 50V  ValueDisplayed: 470pF  [0603]  (hidden comment: GCM1885C1H471JA16D)
C55  VDC_V: 50V  ValueDisplayed: 470pF  [0603]  (hidden comment: GRM1885C1H471JA01D)
C56  VDC_V: 50V  ValueDisplayed: 470pF  [0603]  (hidden comment: GCM1885C1H471JA16D)
C77  VDC_V: 50V  ValueDisplayed: 470pF  [0603]  (hidden comment: GRM1885C1H471JA01D)
C78  VDC_V: 50V  ValueDisplayed: 470pF  [0603]  (hidden comment: GCM1885C1H471JA16D)
C79  VDC_V: 50V  ValueDisplayed: 470pF  [0603]  (hidden comment: GRM1885C1H471JA01D)
C80  VDC_V: 50V  ValueDisplayed: 470pF  [0603]  (hidden comment: GCM1885C1H471JA16D)
C81  VDC_V: 50V  ValueDisplayed: 470pF  [0603]  (hidden comment: GRM1885C1H471JA01D)
C82  VDC_V: 50V  ValueDisplayed: 470pF  [0603]  (hidden comment: GCM1885C1H471JA16D)
C83  VDC_V: 50V  ValueDisplayed: 470pF  [0603]  (hidden comment: GCM1885C1H471JA16D)
C84  VDC_V: 50V  ValueDisplayed: 470pF  [0603]  (hidden comment: GCM1885C1H471JA16D)
C85  VDC_V: 50V  ValueDisplayed: 470pF  [0603]  (hidden comment: GCM1885C1H471JA16D)
C86  VDC_V: 50V  ValueDisplayed: 470pF  [0603]  (hidden comment: GCM1885C1H471JA16D)
C87  ValueDisplayed: 4.7µF  VDC_V: 25V  [0603]  (hidden comment: GRT188C81E475KE13D)
C88  VDC_V: 50V  ValueDisplayed: 0.1µF  [0603]  (hidden comment: CGA3E3X8R1H104K080AE)
C89  VDC_V: 50V  ValueDisplayed: 470pF  [0603]  (hidden comment: GCM1885C1H471JA16D)
C90  VDC_V: 50V  ValueDisplayed: 470pF  [0603]  (hidden comment: GRM1885C1H471JA01D)
C91  VDC_V: 50V  ValueDisplayed: 470pF  [0603]  (hidden comment: GCM1885C1H471JA16D)
C92  ValueDisplayed: 4.7µF  VDC_V: 25V  [0603]  (hidden comment: GRT188C81E475KE13D)
C93  VDC_V: 50V  ValueDisplayed: 0.1µF  [0603]  (hidden comment: CGA3E3X8R1H104K080AE)
C94  VDC_V: 50V  ValueDisplayed: 470pF  [0603]  (hidden comment: GCM1885C1H471JA16D)
C95  VDC_V: 50V  ValueDisplayed: 470pF  [0603]  (hidden comment: GCM1885C1H471JA16D)
J11  801-41-003-10-001000  [Mill-Max_801-41-003-10-001000]
J12  801-41-003-10-001000  [Mill-Max_801-41-003-10-001000]
J13  801-41-003-10-001000  [Mill-Max_801-41-003-10-001000]
R6  ValueDisplayed: 51.1  [0603]  (hidden comment: RC0603FR-0751R1L)
R7  ValueDisplayed: 18.4k  [0603]  (hidden comment: RT0603BRD0718K4L)
R8  ValueDisplayed: 10.0k  [0603]  (hidden comment: RC0603FR-0710KL)
R9  ValueDisplayed: 51.1  [0603]  (hidden comment: RC0603FR-0751R1L)
R10  ValueDisplayed: 43.7k  [0603]  (hidden comment: RT0603DRE0743K7L)
R12  ValueDisplayed: 18.4k  [0603]  (hidden comment: RT0603BRD0718K4L)
R13  ERJ-PB3B6041V  [FP-ERJ-PB3B6041V_0603-MFG]  (value not drawn)
R15  ValueDisplayed: 51.1  [0603]  (hidden comment: RC0603FR-0751R1L)
R28  ERJ-PB3B6041V  [FP-ERJ-PB3B6041V_0603-MFG]  (value not drawn)
R29  ValueDisplayed: 10.0k  [0603]  (hidden comment: RC0603FR-0710KL)
R30  ValueDisplayed: 51.1  [0603]  (hidden comment: RC0603FR-0751R1L)
R31  ValueDisplayed: 51.1  [0603]  (hidden comment: RC0603FR-0751R1L)
R32  ValueDisplayed: 10.0k  [0603]  (hidden comment: RC0603FR-0710KL)
R55  ERJ-PB3B6041V  [FP-ERJ-PB3B6041V_0603-MFG]  (value not drawn)
R56  ValueDisplayed: 10.0k  [0603]  (hidden comment: RC0603FR-0710KL)
R66  ValueDisplayed: 10.0k  [0603]  (hidden comment: RC0603FR-0710KL)
R67  ValueDisplayed: 51.1  [0603]  (hidden comment: RC0603FR-0751R1L)
R68  ERJ-PB3B6041V  [FP-ERJ-PB3B6041V_0603-MFG]  (value not drawn)
R69  ValueDisplayed: 10.0k  [0603]  (hidden comment: RC0603FR-0710KL)
R70  ValueDisplayed: 18.4k  [0603]  (hidden comment: RT0603BRD0718K4L)
R71  ValueDisplayed: 10.0k  [0603]  (hidden comment: RC0603FR-0710KL)
R72  ValueDisplayed: 18.4k  [0603]  (hidden comment: RT0603BRD0718K4L)
R73  ValueDisplayed: 10.0k  [0603]  (hidden comment: RC0603FR-0710KL)
R74  ERJ-PB3B6041V  [FP-ERJ-PB3B6041V_0603-MFG]  (value not drawn)
R75  ERJ-PB3B6041V  [FP-ERJ-PB3B6041V_0603-MFG]  (value not drawn)
R76  ValueDisplayed: 10.0k  [0603]  (hidden comment: RC0603FR-0710KL)
R77  ERJ-PB3B6041V  [FP-ERJ-PB3B6041V_0603-MFG]  (value not drawn)
R78  ValueDisplayed: 10.0k  [0603]  (hidden comment: RC0603FR-0710KL)
R79  ERJ-PB3B6041V  [FP-ERJ-PB3B6041V_0603-MFG]  (value not drawn)
R80  ERJ-PB3B6041V  [FP-ERJ-PB3B6041V_0603-MFG]  (value not drawn)
R81  ValueDisplayed: 51.1  [0603]  (hidden comment: RC0603FR-0751R1L)
R82  ValueDisplayed: 10.0k  [0603]  (hidden comment: RC0603FR-0710KL)
R83  ERJ-PB3B6041V  [FP-ERJ-PB3B6041V_0603-MFG]  (value not drawn)
R84  ValueDisplayed: 10.0k  [0603]  (hidden comment: RC0603FR-0710KL)
R85  ERJ-PB3B6041V  [FP-ERJ-PB3B6041V_0603-MFG]  (value not drawn)
R86  ValueDisplayed: 10.0k  [0603]  (hidden comment: RC0603FR-0710KL)
R87  ValueDisplayed: 10.0k  [0603]  (hidden comment: RC0603FR-0710KL)
U3  TLV9064IPWR  [PW0014A_N]  (parts A,B,C,D,E of 5)
U4  TLV9064IPWR  [PW0014A_N]  (parts A,B,C,D,E of 5)

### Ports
12V_BAT_SENSE, +3.3V, +5_POS, +5_THROTTLE, +5V, +12V_BAT_ISO, AMR_COSN, AMR_COSN_IN, AMR_COSP, AMR_COSP_IN, AMR_SINN, AMR_SINN_IN, AMR_SINP, AMR_SINP_IN, INV_TEMP, MCU_I_PHU, MCU_I_PHV, MCU_I_PHW, MCU_INV_TEMP, MCU_MOTOR_TEMP, MCU_THROTTLE_1, MCU_THROTTLE_2, MOTOR_TEMP, POS_LDO_SENSE, THROTTLE_1, THROTTLE_2, THROTTLE_LDO_SENSE

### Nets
+3.3V: C87.2 C88.1 C92.2 C93.1 R75.1 R80.1 U3.4(V+) U4.4(V+) ; port +3.3V
+5V: J11.1 J12.1 J13.1 ; port +5V
GND: C20.1 C21.2 C22.2 C54.1 C55.2 C56.1 C77.2 C78.1 C79.2 C80.1 C81.2 C82.1 C83.1 C84.1 C85.1 C86.1 C87.1 C88.2 C89.1 C90.2 C91.1 C92.1 C93.2 C94.1 C95.1 J11.2 J12.2 J13.2 R8.1 R29.1 R32.1 R56.1 R66.1 R69.1 R71.1 R73.1 R76.1 R78.1 R82.1 R84.1 R86.1 R87.1 U3.11(V-) U4.11(V-)
12V_BAT_SENSE: C95.2 R10.2 R87.2 ; port 12V_BAT_SENSE
+5_POS: R70.1 ; port +5_POS
+5_THROTTLE: R72.1 ; port +5_THROTTLE
+12_Bat_Iso: R10.1 ; port +12V_BAT_ISO
AMR_COS_N: C94.2 R85.2 R86.2 ; port AMR_COSN
AMR_COS_P: C89.2 R79.2 R82.2 ; port AMR_COSP
AMR_COSN_IN: R85.1 ; port AMR_COSN_IN
AMR_COSP_IN: R79.1 ; port AMR_COSP_IN
AMR_SIN_N: C86.2 R77.2 R78.2 ; port AMR_SINN
AMR_SIN_P: C85.2 R74.2 R76.2 ; port AMR_SINP
AMR_SINN_IN: R77.1 ; port AMR_SINN_IN
AMR_SINP_IN: R74.1 ; port AMR_SINP_IN
ILEM_A_MCU: C21.1 R30.2 ; port MCU_I_PHU
ILEM_B_MCU: C22.1 R15.2 ; port MCU_I_PHV
ILEM_C_MCU: C55.1 R31.2 ; port MCU_I_PHW
INV_TEMP: R83.1 ; port INV_TEMP
IPH_U_IN: J11.3 R13.1
IPH_V_IN: J12.3 R28.1
IPH_W_IN: J13.3 R55.1
MCU_INV_TEMP: C90.1 R81.2 ; port MCU_INV_TEMP
MCU_MOTOR_TEMP: C81.1 R67.2 ; port MCU_MOTOR_TEMP
MCU_THROTTLE_1: C77.1 R6.2 ; port MCU_THROTTLE_1
MCU_THROTTLE_2: C79.1 R9.2 ; port MCU_THROTTLE_2
MOTOR_TEMP: R68.1 ; port MOTOR_TEMP
POS_LDO_SENSE: C83.2 R70.2 R71.2 ; port POS_LDO_SENSE
THROTTLE_1: R7.1 ; port THROTTLE_1
THROTTLE_2: R12.1 ; port THROTTLE_2
THROTTLE_LDO_SENSE: C84.2 R72.2 R73.2 ; port THROTTLE_LDO_SENSE
NetC20_2: C20.2 R13.2 R32.2 U3.3(IN+)
NetC54_2: C54.2 R28.2 R29.2 U3.10(IN+)
NetC56_2: C56.2 R55.2 R56.2 U3.12(IN+)
NetC78_2: C78.2 R7.2 R8.2 U3.5(IN+)
NetC80_2: C80.2 R12.2 R66.2 U4.3(IN+)
NetC82_2: C82.2 R68.2 R69.2 R75.2 U4.5(IN+)
NetC91_2: C91.2 R80.2 R83.2 R84.2 U4.10(IN+)
NetR6_1: R6.1 U3.6(IN-) U3.7(OUT)
NetR9_1: R9.1 U4.1(OUT) U4.2(IN-)
NetR15_1: R15.1 U3.8(OUT) U3.9(IN-)
NetR30_1: R30.1 U3.1(OUT) U3.2(IN-)
NetR31_1: R31.1 U3.13(IN-) U3.14(OUT)
NetR67_1: R67.1 U4.6(IN-) U4.7(OUT)
NetR81_1: R81.1 U4.8(OUT) U4.9(IN-)

Not connected (* = marked no-connect by the designer): U4 12(IN+)* 13(IN-)* 14(OUT)*

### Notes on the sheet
- Calculated cutoff frequency for Iph filter = ~89.1kHz
- Placed close to control card

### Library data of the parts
C20 C54 C56 C78 C80 C82-C86 C89 C91 C94 C95 = CMP-0007127-4: CAP, CERM, 470 pF, 50 V, +/- 5%, C0G/NP0, AEC-Q200 Grade 1, 0603; Manufacturer: MuRata; TaMin_C: -55°C; Polarized: N; SizeAreaWB_mm2: 4.68; Value1: Unknown; U/M: EA; Value: 470pF; TaMax_C: 125°C; SizeZ_mm: 1; SizeX_mm: 1.6; SizeY_mm: 0.8; SizeArea_mm2: 1.28; AEC Qualified: Y; AEC Category: Q200
C21 C22 C55 C77 C79 C81 C90 = CMP-0007221-4: CAP, CERM, 470 pF, 50 V, +/- 5%, C0G/NP0, 0603; Manufacturer: MuRata; TaMin_C: -55°C; Polarized: N; SizeAreaWB_mm2: 4.68; Value1: Unknown; U/M: EA; Value: 470pF; TaMax_C: 125°C; SizeZ_mm: 1; SizeX_mm: 1.6; SizeY_mm: 0.8; SizeArea_mm2: 1.28; AEC Category: Q200
C87 C92 = CMP-0085645-1: CAP, CERM, 4.7 µF, 25 V,+/- 10%, X6S, AEC-Q200 Grade 2, 0603; Manufacturer: MuRata; TaMax_C: 105°C; SizeY_mm: 0.8; AEC Grade: 2; Polarized: N; SizeZ_mm: 1; SizeArea_mm2: 1.28; U/M: EA; SizeAreaWB_mm2: 4.68; SizeX_mm: 1.6; TaMin_C: -55°C; AEC Qualified: Y; AEC Category: Q200; Value: 4.7uF
C88 C93 = CMP-0079911-1: as C34 on sheet CAN_Comm
J11-J13 = CMP-0076709-1: Receptacle, 2.54mm, 3x1, Gold, TH; Manufacturer: Mill-Max; Pitch_mm: 2.54; Gender: Female; CT: True; Row_Count: 1; CompType: Socket Strip; CNHeader: False; System: Connector
R6 R9 R15 R30 R31 R67 R81 = CMP-0023168-5: RES, 51.1, 1%, 0.1 W, 0603; Manufacturer: Yageo; Power_W: 100mW; TempCo: 100 ppm/C; Value_Code: 51R1; Value: 51.1; EIA_Code: E96; SizeX_mm: 1.6; SizeY_mm: 0.8; SizeZ_mm: 1; Value2: 0.1W; SizeArea_mm2: 1.28; AEC Qualified: N; VDC_V: 75V; AEC Category: Q200; SizeAreaWB_mm2: 4.68
R7 R12 R70 R72 = CMP-0023837-2: RES, 18.4 k, 0.1%, 0.1 W, 0603; Manufacturer: Yageo America; Power_W: 100mW; EIA_Code: E192; Value_Code: 18k4; SizeY_mm: 0.8; SizeZ_mm: 1; SizeArea_mm2: 1.28; TempCo: 25 ppm/C; Value: 18.4k; SizeX_mm: 1.6; Value2: 0.1W; VDC_V: 75V; AEC Category: Q200; U/M: EA
R8 R29 R32 R56 R66 R69 R71 R73 R76 R78 R82 R84 R86 R87 = CMP-0022746-5: RES, 10.0 k, 1%, 0.1 W, 0603; Manufacturer: Yageo; Power_W: 100mW; TempCo: 100 ppm/C; Value_Code: 10k0; Value: 10.0k; EIA_Code: E96; Res_ohm: 10k; SizeX_mm: 1.6; SizeY_mm: 0.8; SizeZ_mm: 1; Value2: 0.1W; SizeArea_mm2: 1.28; AEC Qualified: N; VDC_V: 75V; AEC Category: Q200; SizeAreaWB_mm2: 4.68
R10 = CMP-0025288-2: RES, 43.7 k, 0.5%, 0.1 W, 0603; Manufacturer: Yageo America; Power_W: 100mW; EIA_Code: E192; Value_Code: 43k7; SizeY_mm: 0.8; SizeZ_mm: 1; SizeArea_mm2: 1.28; TempCo: 50 ppm/C; Value: 43.7k; SizeX_mm: 1.6; Value2: 0.1W; VDC_V: 75V; AEC Category: Q200; U/M: EA
R13 R28 R55 R68 R74 R75 R77 R79 R80 R83 R85 = CMP-0088378-2: 6.04 kOhms ±0.1% 0.2W, 1/5W Chip Resistor 0603 (1608 Metric) Automotive AEC-Q200, Pulse Withstanding Thick Film; Manufacturer: Panasonic; Power_W: 200mW; AEC Qualified: Yes; SizeZ_mm: 0.55mm; AEC Grade: Grade 0; TempCo: 50ppm/°C; Res_ohm: 6.04k; VDC_V: 150V
U3 U4 = CMP-0082283-1: 4 channel, 10-MHz, Low-Noise, RRIO, CMOS Operational Amplifier for Cost-Sensitive Systems, PW0014A (TSSOP-14); Alternate PartNumber: TLV9064IPWT; Alternate Manufacturer: Texas Instruments; SizeAreaWB_mm2: 58.8; Rating: Catalog; SizeZ_mm: 1.2; SizeX_mm: 6.4; SizeY_mm: 5; SizeArea_mm2: 32; CompType: IC; AEC Qualified: N; AEC Category: Q200

## Sheet Gate_Drive.SchDoc
size 431 x 279 mm; Date: Not shown in title block; ApprovedBy: Not shown in title block; CheckedBy: Not shown in title block; Author: Not shown in title block; CompanyName: Not shown in title block; Engineer: Not shown in title block; Organization: Not shown in title block; Address1: Not shown in title block; Address2: Not shown in title block; Address3: Not shown in title block; Address4: Not shown in title block; DocumentNumber: 2; Revision: Use project parameter SCH_Rev; SheetNumber: 2; SheetTotal: 3; PageSetup: Record=PageOptions¦CenterHorizontal=True¦CenterVertical=True¦PrintScale=1.00¦XCorrection=1.00¦YCorrection=1.00¦PrintKind=0¦BorderSize=5000000¦LeftOffset=0¦BottomOffset=0¦Orientation=2¦PaperLength=1000¦PaperWidth=1000¦Scale=100¦PaperSource=15¦PrintQuality=600¦MediaType=1¦DitherType=10¦PaperKind=Letter¦PrintScaleMode=1
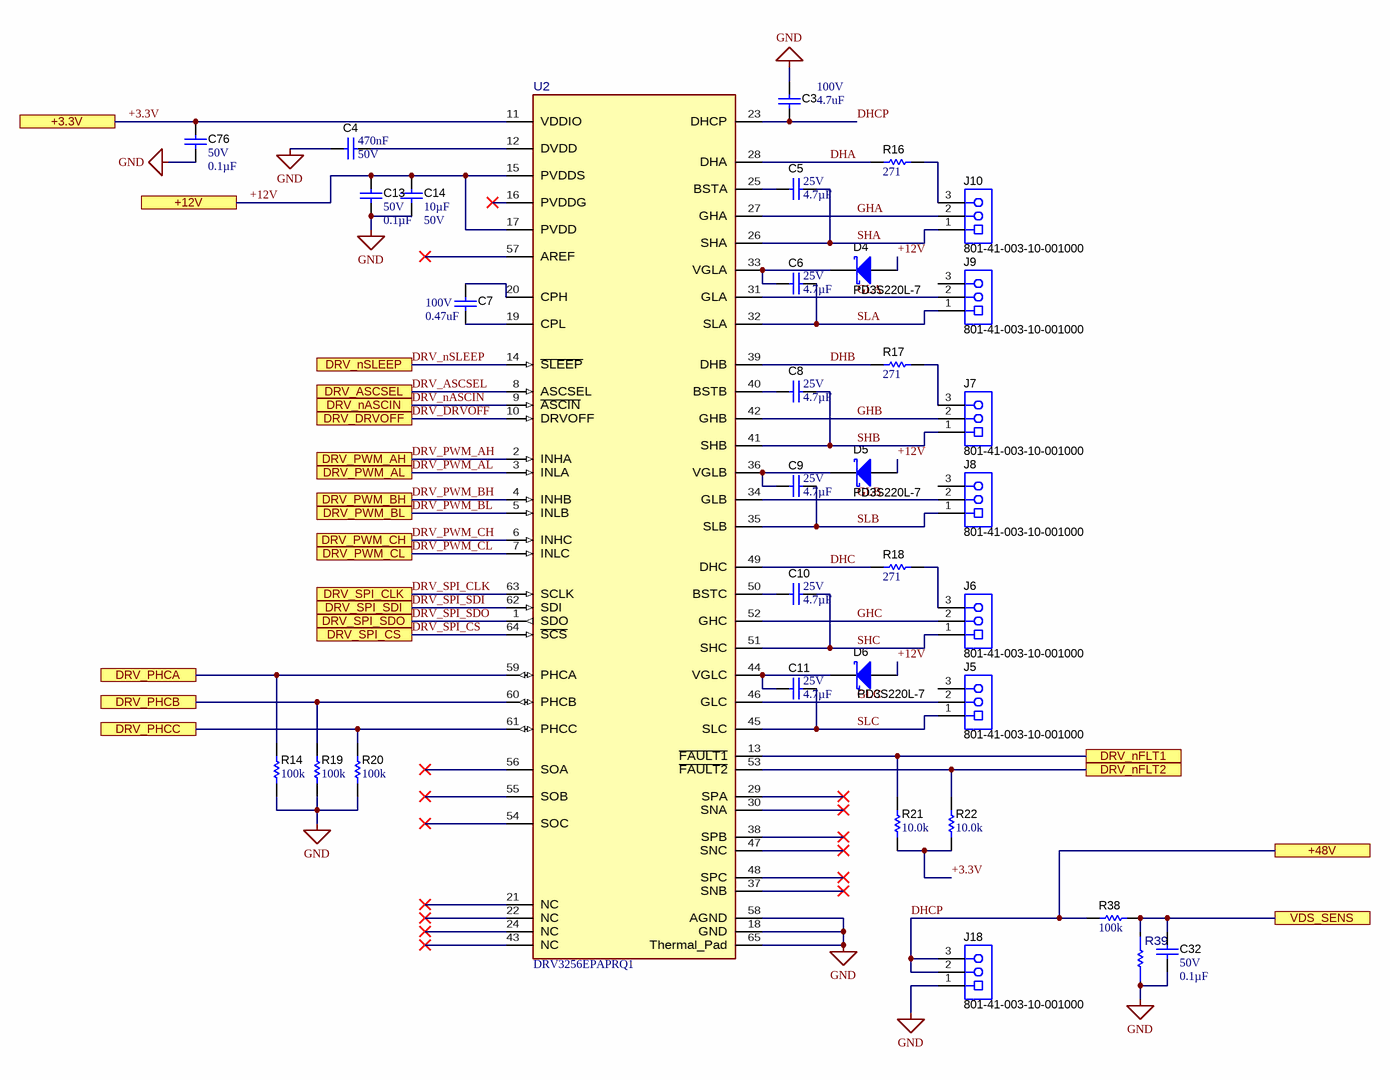
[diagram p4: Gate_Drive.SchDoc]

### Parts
C3  VDC_V: 100V  ValueDisplayed: 4.7uF  [2220_250]  (hidden comment: CGA9N2X7R2A475M230KA)
C4  Cap_F: 470nF  VDC_V: 50V  [0603]  (hidden comment: CGA3E3X7R1H474M080AE)
C5  ValueDisplayed: 4.7µF  VDC_V: 25V  [0603]  (hidden comment: GRT188C81E475KE13D)
C6  ValueDisplayed: 4.7µF  VDC_V: 25V  [0603]  (hidden comment: GRT188C81E475KE13D)
C7  VDC_V: 100V  ValueDisplayed: 0.47uF  [1206_180]  (hidden comment: CGA5L2X7R2A474K160AA)
C8  ValueDisplayed: 4.7µF  VDC_V: 25V  [0603]  (hidden comment: GRT188C81E475KE13D)
C9  ValueDisplayed: 4.7µF  VDC_V: 25V  [0603]  (hidden comment: GRT188C81E475KE13D)
C10  ValueDisplayed: 4.7µF  VDC_V: 25V  [0603]  (hidden comment: GRT188C81E475KE13D)
C11  ValueDisplayed: 4.7µF  VDC_V: 25V  [0603]  (hidden comment: GRT188C81E475KE13D)
C13  VDC_V: 50V  ValueDisplayed: 0.1µF  [0603]  (hidden comment: CGA3E3X8R1H104K080AE)
C14  ValueDisplayed: 10µF  VDC_V: 50V  [1206_190]  (hidden comment: CGA5L1X7R1H106K160AC)
C32  VDC_V: 50V  ValueDisplayed: 0.1µF  [0603]  (hidden comment: CGA3E3X8R1H104K080AE)
C76  VDC_V: 50V  ValueDisplayed: 0.1µF  [0603]  (hidden comment: CGA3E3X8R1H104K080AE)
D4  PD3S220L-7  [PowerDI323]
D5  PD3S220L-7  [PowerDI323]
D6  PD3S220L-7  [PowerDI323]
J5  801-41-003-10-001000  [Mill-Max_801-41-003-10-001000]
J6  801-41-003-10-001000  [Mill-Max_801-41-003-10-001000]
J7  801-41-003-10-001000  [Mill-Max_801-41-003-10-001000]
J8  801-41-003-10-001000  [Mill-Max_801-41-003-10-001000]
J9  801-41-003-10-001000  [Mill-Max_801-41-003-10-001000]
J10  801-41-003-10-001000  [Mill-Max_801-41-003-10-001000]
J18  801-41-003-10-001000  [Mill-Max_801-41-003-10-001000]
R14  ValueDisplayed: 100k  [0603]  (hidden comment: ERA-3ARW104V)
R16  ValueDisplayed: 271  [0603]  (hidden comment: RT0603BRD07271RL)
R17  ValueDisplayed: 271  [0603]  (hidden comment: RT0603BRD07271RL)
R18  ValueDisplayed: 271  [0603]  (hidden comment: RT0603BRD07271RL)
R19  ValueDisplayed: 100k  [0603]  (hidden comment: ERA-3ARW104V)
R20  ValueDisplayed: 100k  [0603]  (hidden comment: ERA-3ARW104V)
R21  ValueDisplayed: 10.0k  [0603]  (hidden comment: RMCF0603FT10K0)
R22  ValueDisplayed: 10.0k  [0603]  (hidden comment: RMCF0603FT10K0)
R38  ValueDisplayed: 100k  [0603]  (hidden comment: ERA-3ARW104V)
R39  ERJ-PB3B6041V  [FP-ERJ-PB3B6041V_0603-MFG]  (value not drawn)
U2  DRV3256EPAPRQ1  [PAP0064N-MFG]

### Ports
+3.3V, +12V, +48V, DRV_ASCSEL, DRV_DRVOFF, DRV_nASCIN, DRV_nFLT1, DRV_nFLT2, DRV_nSLEEP, DRV_PHCA, DRV_PHCB, DRV_PHCC, DRV_PWM_AH, DRV_PWM_AL, DRV_PWM_BH, DRV_PWM_BL, DRV_PWM_CH, DRV_PWM_CL, DRV_SPI_CLK, DRV_SPI_CS, DRV_SPI_SDI, DRV_SPI_SDO, VDS_SENS

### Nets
+3.3V: C76.1 R21.1 R22.1 U2.11(VDDIO) ; port +3.3V
GND: C3.1 C4.2 C13.2 C14.2 C32.1 C76.2 J18.1 R14.1 R19.1 R20.1 R39.1 U2.18(GND) U2.58(AGND) U2.65(Thermal_Pad)
+12V: C13.1 C14.1 D4.2(A) D5.2(A) D6.2(A) U2.15(PVDDS) U2.17(PVDD) ; port +12V
DHA: R16.1 U2.28(DHA)
DHB: R17.1 U2.39(DHB)
DHC: R18.1 U2.49(DHC)
DHCP: C3.2 J18.2 J18.3 R38.1 U2.23(DHCP) ; port +48V  [project net +48V]
DRV_ASCSEL: U2.8(ASCSEL) ; port DRV_ASCSEL
DRV_DRVOFF: U2.10(DRVOFF) ; port DRV_DRVOFF
DRV_nASCIN: U2.9(~{ASCIN}) ; port DRV_nASCIN
DRV_nFLT1: R21.2 U2.13(~{FAULT1}) ; port DRV_nFLT1
DRV_nFLT2: R22.2 U2.53(~{FAULT2}) ; port DRV_nFLT2
DRV_nSLEEP: U2.14(~{SLEEP}) ; port DRV_nSLEEP
DRV_PHCA: R14.2 U2.59(PHCA) ; port DRV_PHCA
DRV_PHCB: R19.2 U2.60(PHCB) ; port DRV_PHCB
DRV_PHCC: R20.2 U2.61(PHCC) ; port DRV_PHCC
DRV_PWM_AH: U2.2(INHA) ; port DRV_PWM_AH
DRV_PWM_AL: U2.3(INLA) ; port DRV_PWM_AL
DRV_PWM_BH: U2.4(INHB) ; port DRV_PWM_BH
DRV_PWM_BL: U2.5(INLB) ; port DRV_PWM_BL
DRV_PWM_CH: U2.6(INHC) ; port DRV_PWM_CH
DRV_PWM_CL: U2.7(INLC) ; port DRV_PWM_CL
DRV_SPI_CLK: U2.63(SCLK) ; port DRV_SPI_CLK
DRV_SPI_CS: U2.64(~{SCS}) ; port DRV_SPI_CS
DRV_SPI_SDI: U2.62(SDI) ; port DRV_SPI_SDI
DRV_SPI_SDO: U2.1(SDO) ; port DRV_SPI_SDO
GHA: J10.2 U2.27(GHA)
GHB: J7.2 U2.42(GHB)
GHC: J6.2 U2.52(GHC)
GLA: J9.2 U2.31(GLA)
GLB: J8.2 U2.34(GLB)
GLC: J5.2 U2.46(GLC)
SHA: C5.1 J10.1 U2.26(SHA)
SHB: C8.1 J7.1 U2.41(SHB)
SHC: C10.1 J6.1 U2.51(SHC)
SLA: C6.1 J9.1 U2.32(SLA)
SLB: C9.1 J8.1 U2.35(SLB)
SLC: C11.1 J5.1 U2.45(SLC)
VDC: C32.2 R38.2 R39.2 ; port VDS_SENS
NetC4_1: C4.1 U2.12(DVDD)
NetC5_2: C5.2 U2.25(BSTA)
NetC6_2: C6.2 D4.1(K) U2.33(VGLA)
NetC7_1: C7.1 U2.20(CPH)
NetC7_2: C7.2 U2.19(CPL)
NetC8_2: C8.2 U2.40(BSTB)
NetC9_2: C9.2 D5.1(K) U2.36(VGLB)
NetC10_2: C10.2 U2.50(BSTC)
NetC11_2: C11.2 D6.1(K) U2.44(VGLC)
NetJ6_3: J6.3 R18.2
NetJ7_3: J7.3 R17.2
NetJ10_3: J10.3 R16.2

Not connected (* = marked no-connect by the designer): J5 3; J8 3; J9 3; U2 16(PVDDG)* 21(NC)* 22(NC)* 24(NC)* 29(SPA)* 30(SNA)* 37(SNB)* 38(SPB)* 43(NC)* 47(SNC)* 48(SPC)* 54(SOC)* 55(SOB)* 56(SOA)* 57(AREF)*

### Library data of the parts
C3 = CMP-0009414-2: CAP, CERM, 4.7 uF, 100 V, +/- 20%, X7R, AEC-Q200 Grade 1,; Manufacturer: TDK; TaMin_C: -55°C; Polarized: N; SizeAreaWB_mm2: 53.9; Value1: Unknown; U/M: EA; Value: 4.7uF; TaMax_C: 125°C; SizeZ_mm: 2.5; SizeX_mm: 5.7; SizeY_mm: 5; Cap_Case: 2220; SizeArea_mm2: 28.5; AEC Qualified: Y; Cap_F: 4.7µF; AEC Grade: 1; AEC Category: Q200
C4 = CMP-0007098-4: CAP, CERM, 0.47 uF, 50 V, +/- 20%, X7R, AEC-Q200 Grade 1, 0603; Manufacturer: TDK; TaMin_C: -55°C; Polarized: N; SizeAreaWB_mm2: 4.68; Value1: Unknown; U/M: EA; Value: 0.47uF; TaMax_C: 125°C; SizeZ_mm: 1; SizeX_mm: 1.6; SizeY_mm: 0.8; SizeArea_mm2: 1.28; AEC Qualified: Y; AEC Category: Q200
C5 C6 C8-C11 = CMP-0085645-1: as C87 on sheet Input_Signal_Conditioning
C7 = CMP-0008781-2: CAP, CERM, 0.47 uF, 100 V, +/- 10%, X7R, AEC-Q200 Grade 1, 1206; Manufacturer: TDK; TaMin_C: -55°C; ESR_ohm: 7.558m; Polarized: N; SizeAreaWB_mm2: 10.92; Value1: 0.007558 ohm; U/M: EA; Value: 0.47uF; TaMax_C: 125°C; SizeZ_mm: 1.8; SizeX_mm: 3.2; SizeY_mm: 1.6; SizeArea_mm2: 5.12; AEC Qualified: Y; Cap_F: 470nF; IRMS_A: 2.6472A; AEC Grade: 1; AEC Category: Q200
C13 C32 C76 = CMP-0079911-1: as C34 on sheet CAN_Comm
C14 = CMP-0085950-1: as C33 on sheet CAN_Comm
D4-D6 = CMP-0080709-2: Diode, Schottky, 20 V, 2 A, AEC-Q101, PowerDI323; Manufacturer: Diodes Inc.; SizeArea_mm2: 3.125; Value1: 2A; Value2: 0.47V; SizeX_mm: 2.5; TJmax_C: 125°C; Value: 20V; Vf_V: 470mV; SizeZ_mm: 0.7; AEC Category: Q101; SizeAreaWB_mm2: 7.875; SizeY_mm: 1.25; AEC Qualified: Y
J5-J10 J18 = CMP-0076709-1: as J11 on sheet Input_Signal_Conditioning
R14 R19 R20 R38 = CMP-0023385-3: RES, 100 k, 0.05%, 0.1 W, AEC-Q200 Grade 0, 0603; Manufacturer: Panasonic; Power_W: 100mW; TempCo: 10 ppm/C; U/M: EA; Value: 100k; SizeX_mm: 1.6; SizeY_mm: 0.8; SizeZ_mm: 1; Value2: 0.1W; SizeArea_mm2: 1.28; AEC Qualified: Y; VDC_V: 75V; AEC Grade: 0; AEC Category: Q200
R16-R18 = CMP-0024021-2: RES, 271, 0.1%, 0.1 W, 0603; Manufacturer: Yageo America; Power_W: 100mW; TempCo: 25 ppm/C; Value_Code: 271R; U/M: EA; Value: 271; EIA_Code: E192; SizeX_mm: 1.6; SizeY_mm: 0.8; SizeZ_mm: 1; Value2: 0.1W; SizeArea_mm2: 1.28; VDC_V: 75V; AEC Category: Q200
R21 R22 = CMP-0023341-3: RES, 10.0 k, 1%, 0.1 W, AEC-Q200 Grade 0, 0603; Manufacturer: Stackpole Electronics Inc; Power_W: 100mW; TempCo: 100 ppm/C; Value_Code: 10k0; U/M: EA; Value: 10.0k; EIA_Code: E96; Res_ohm: 10k; SizeX_mm: 1.6; SizeY_mm: 0.8; SizeZ_mm: 1; Value2: 0.1W; SizeArea_mm2: 1.28; AEC Qualified: Y; VDC_V: 75V; AEC Grade: 0; AEC Category: Q200
R39 = CMP-0088378-2: as R13 on sheet Input_Signal_Conditioning
U2 = CMP-0089128-1: 3-Phase 48-V Automotive Gate Driver Unit (GDU) with Advanced Protection and Diagnostics; Manufacturer: Texas Instruments; Propagation Delay: 90ns; Standoff Height: 0.05mm; TaMin_C: -40°C; Min Supply Voltage: 3V; TaMax_C: +150°C; SizeZ_mm: 1.2mm; AEC Qualified: Yes; TJmax_C: +175°C; Max Supply Voltage: 15V; Number Of Drivers: 3; AEC Grade: Grade 0; Nominal Supply Current: 15-24mA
